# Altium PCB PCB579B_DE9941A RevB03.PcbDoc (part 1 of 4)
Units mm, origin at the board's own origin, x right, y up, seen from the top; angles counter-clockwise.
Board outline 85.8 x 54.18 mm, 6 copper layers (Top, L2C, L3C, L4C, L5C, Bottom), stack 1.627 mm thick; 536 components, 371 nets, 1413 pads, 798 vias.
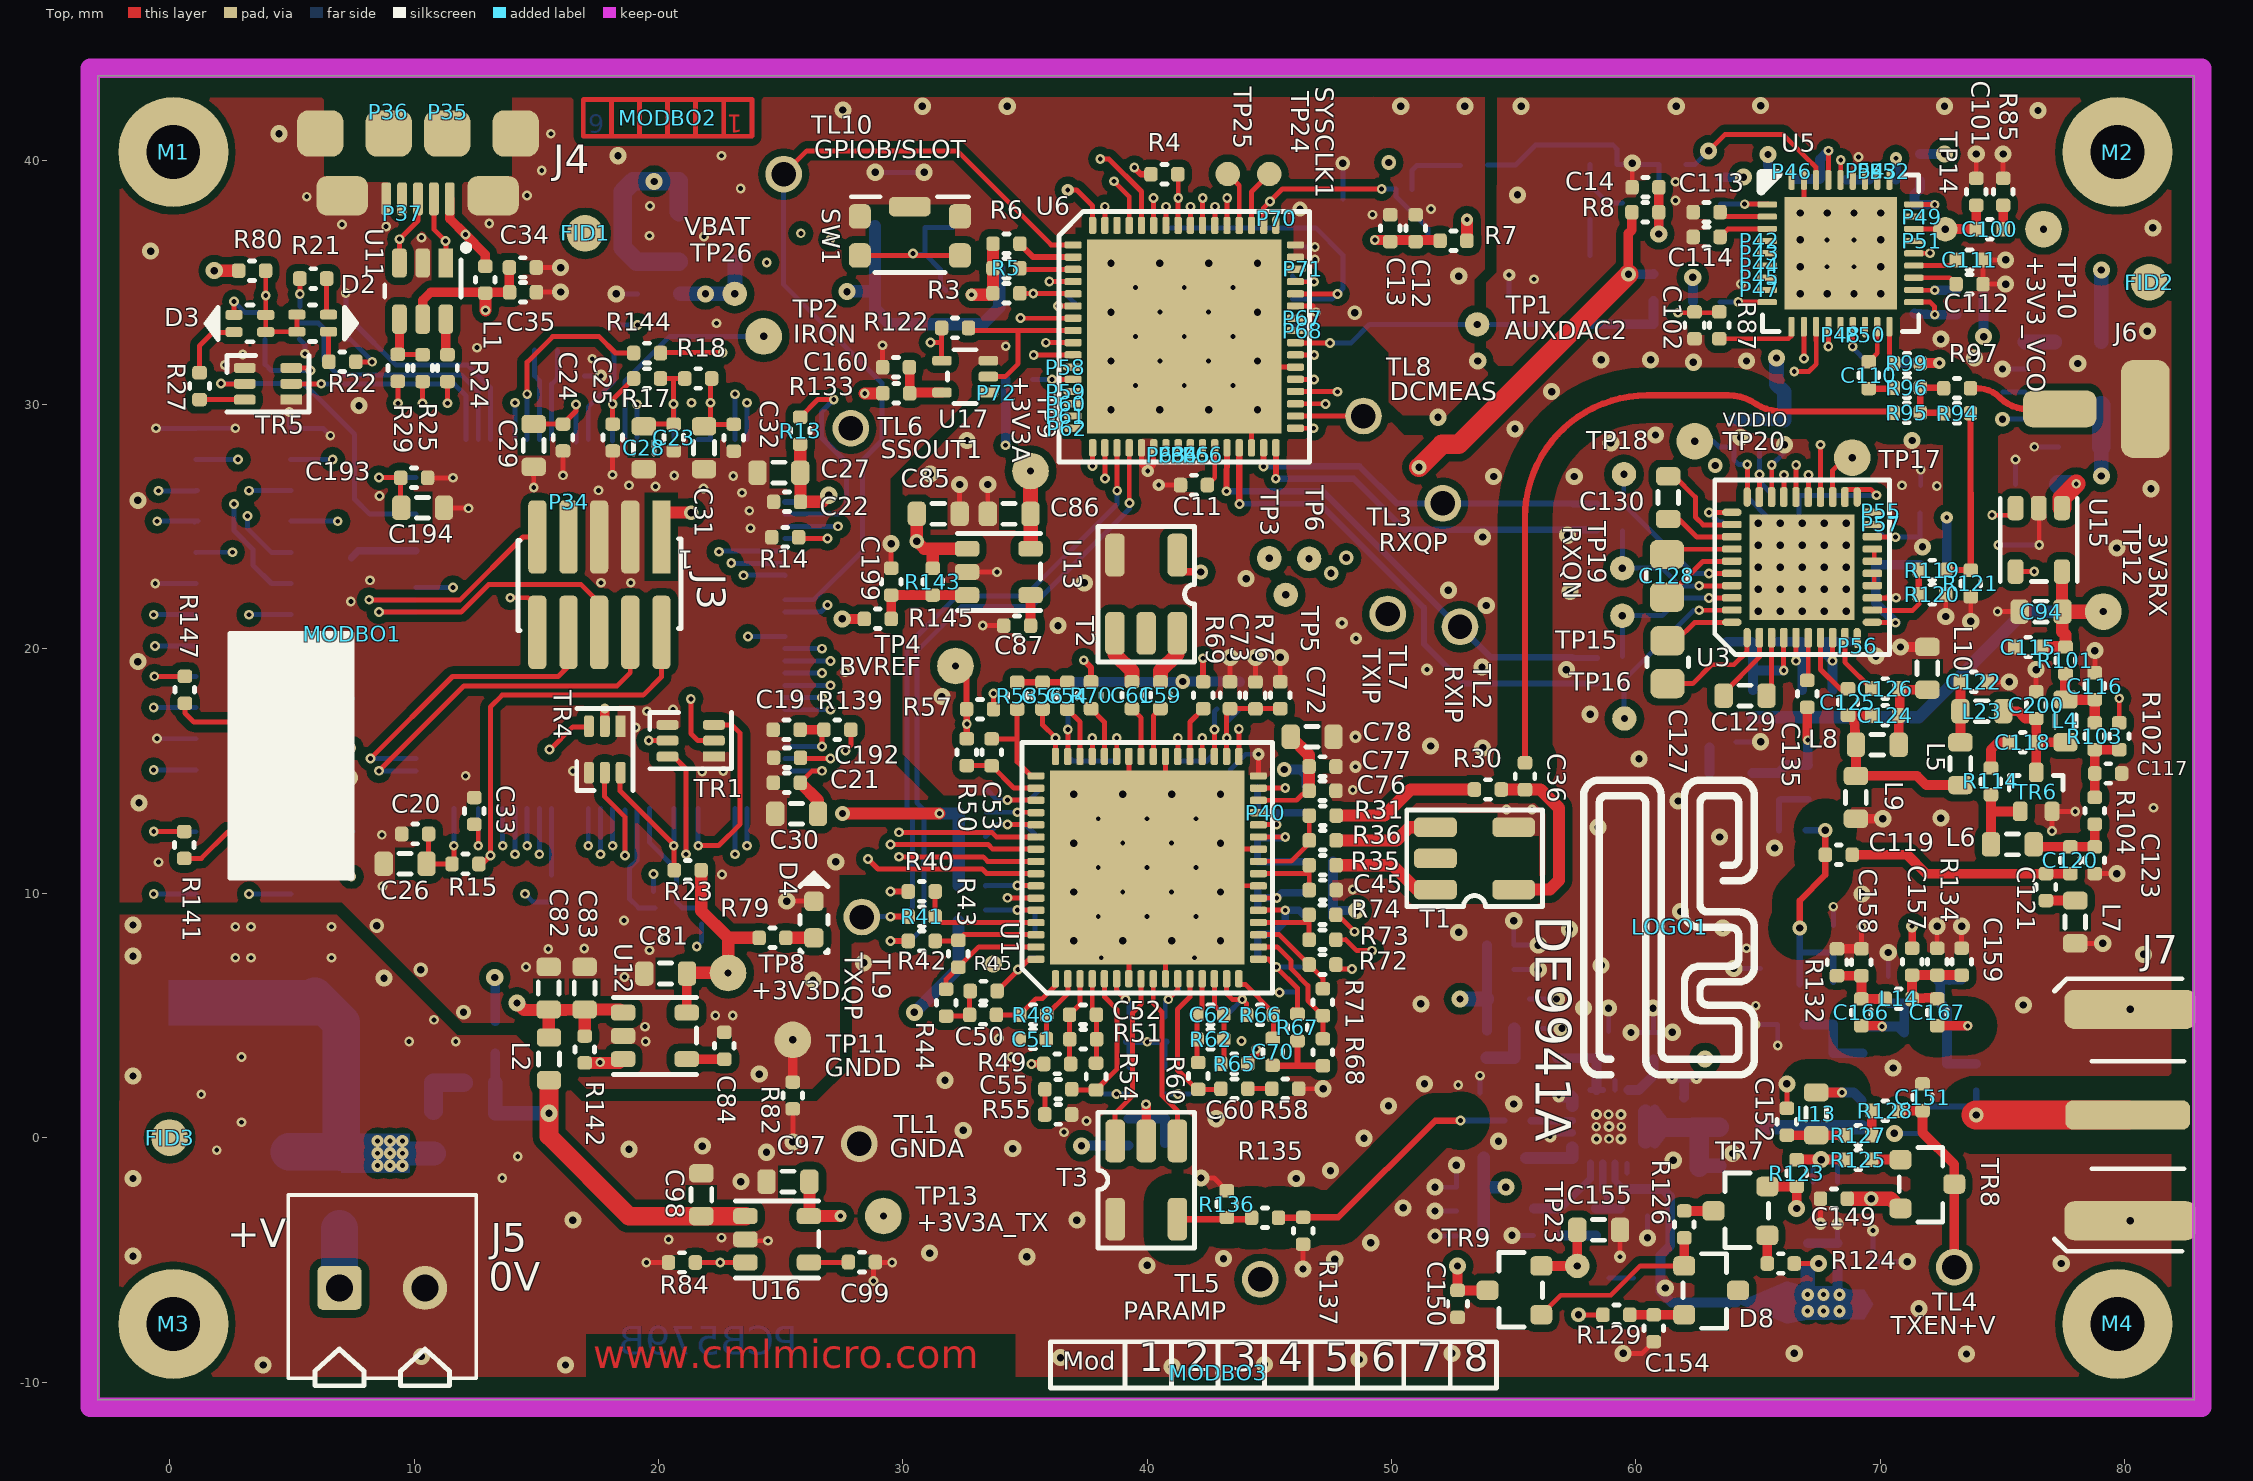
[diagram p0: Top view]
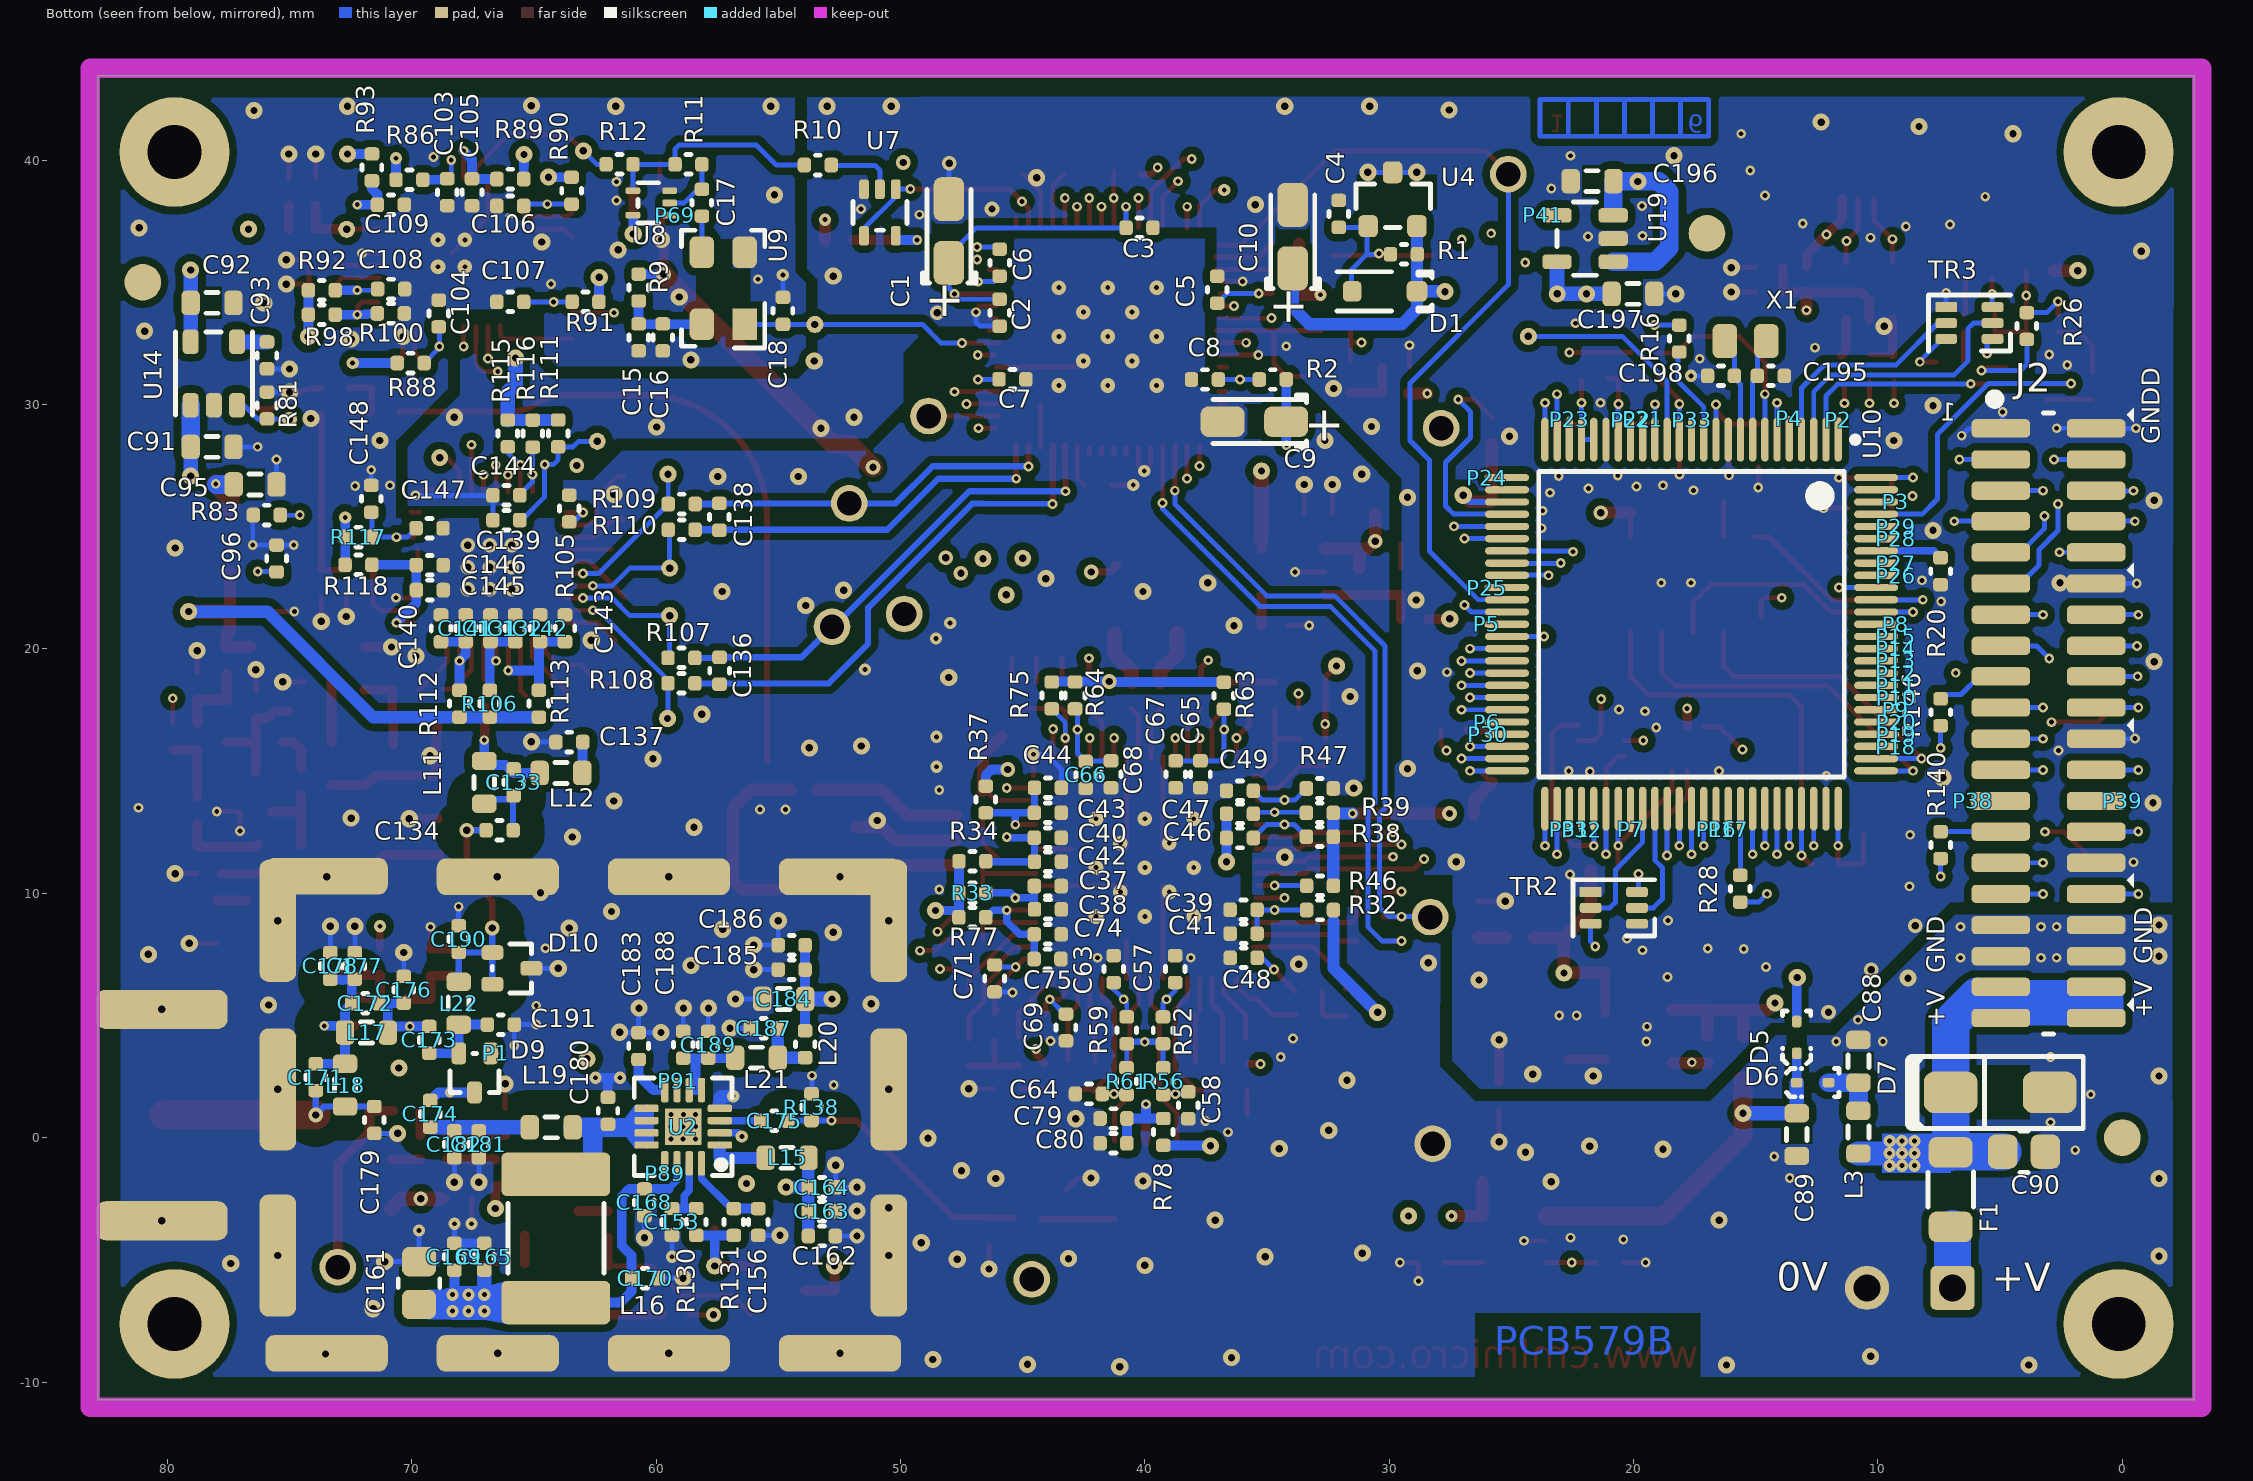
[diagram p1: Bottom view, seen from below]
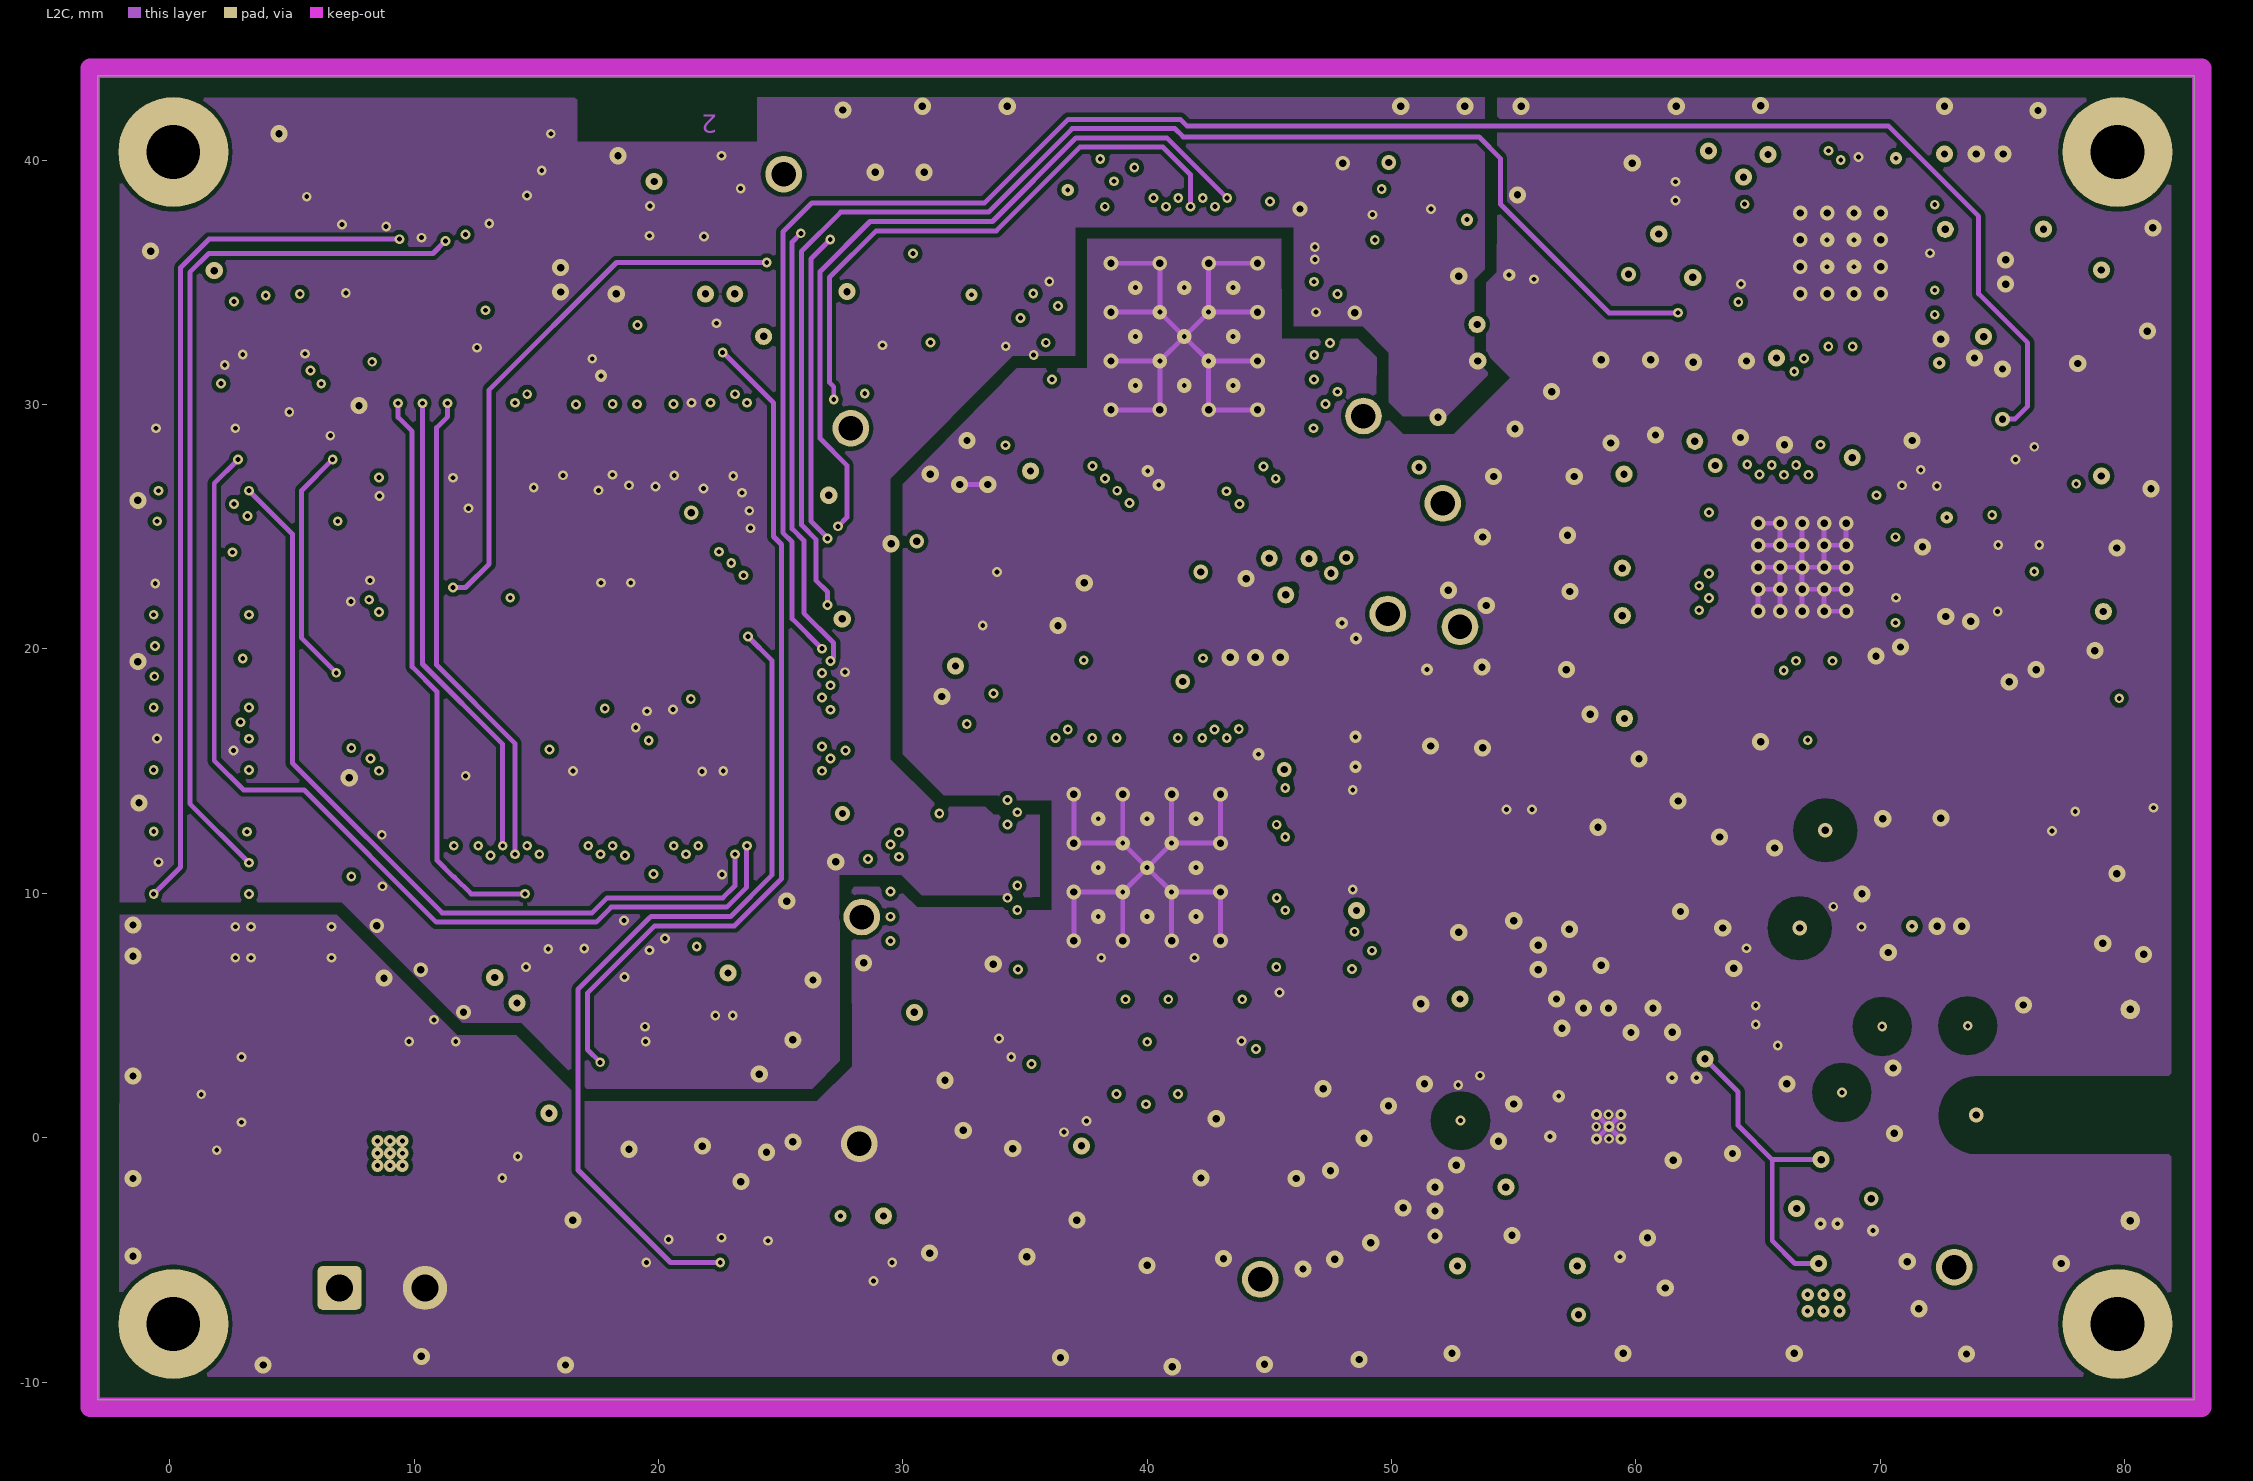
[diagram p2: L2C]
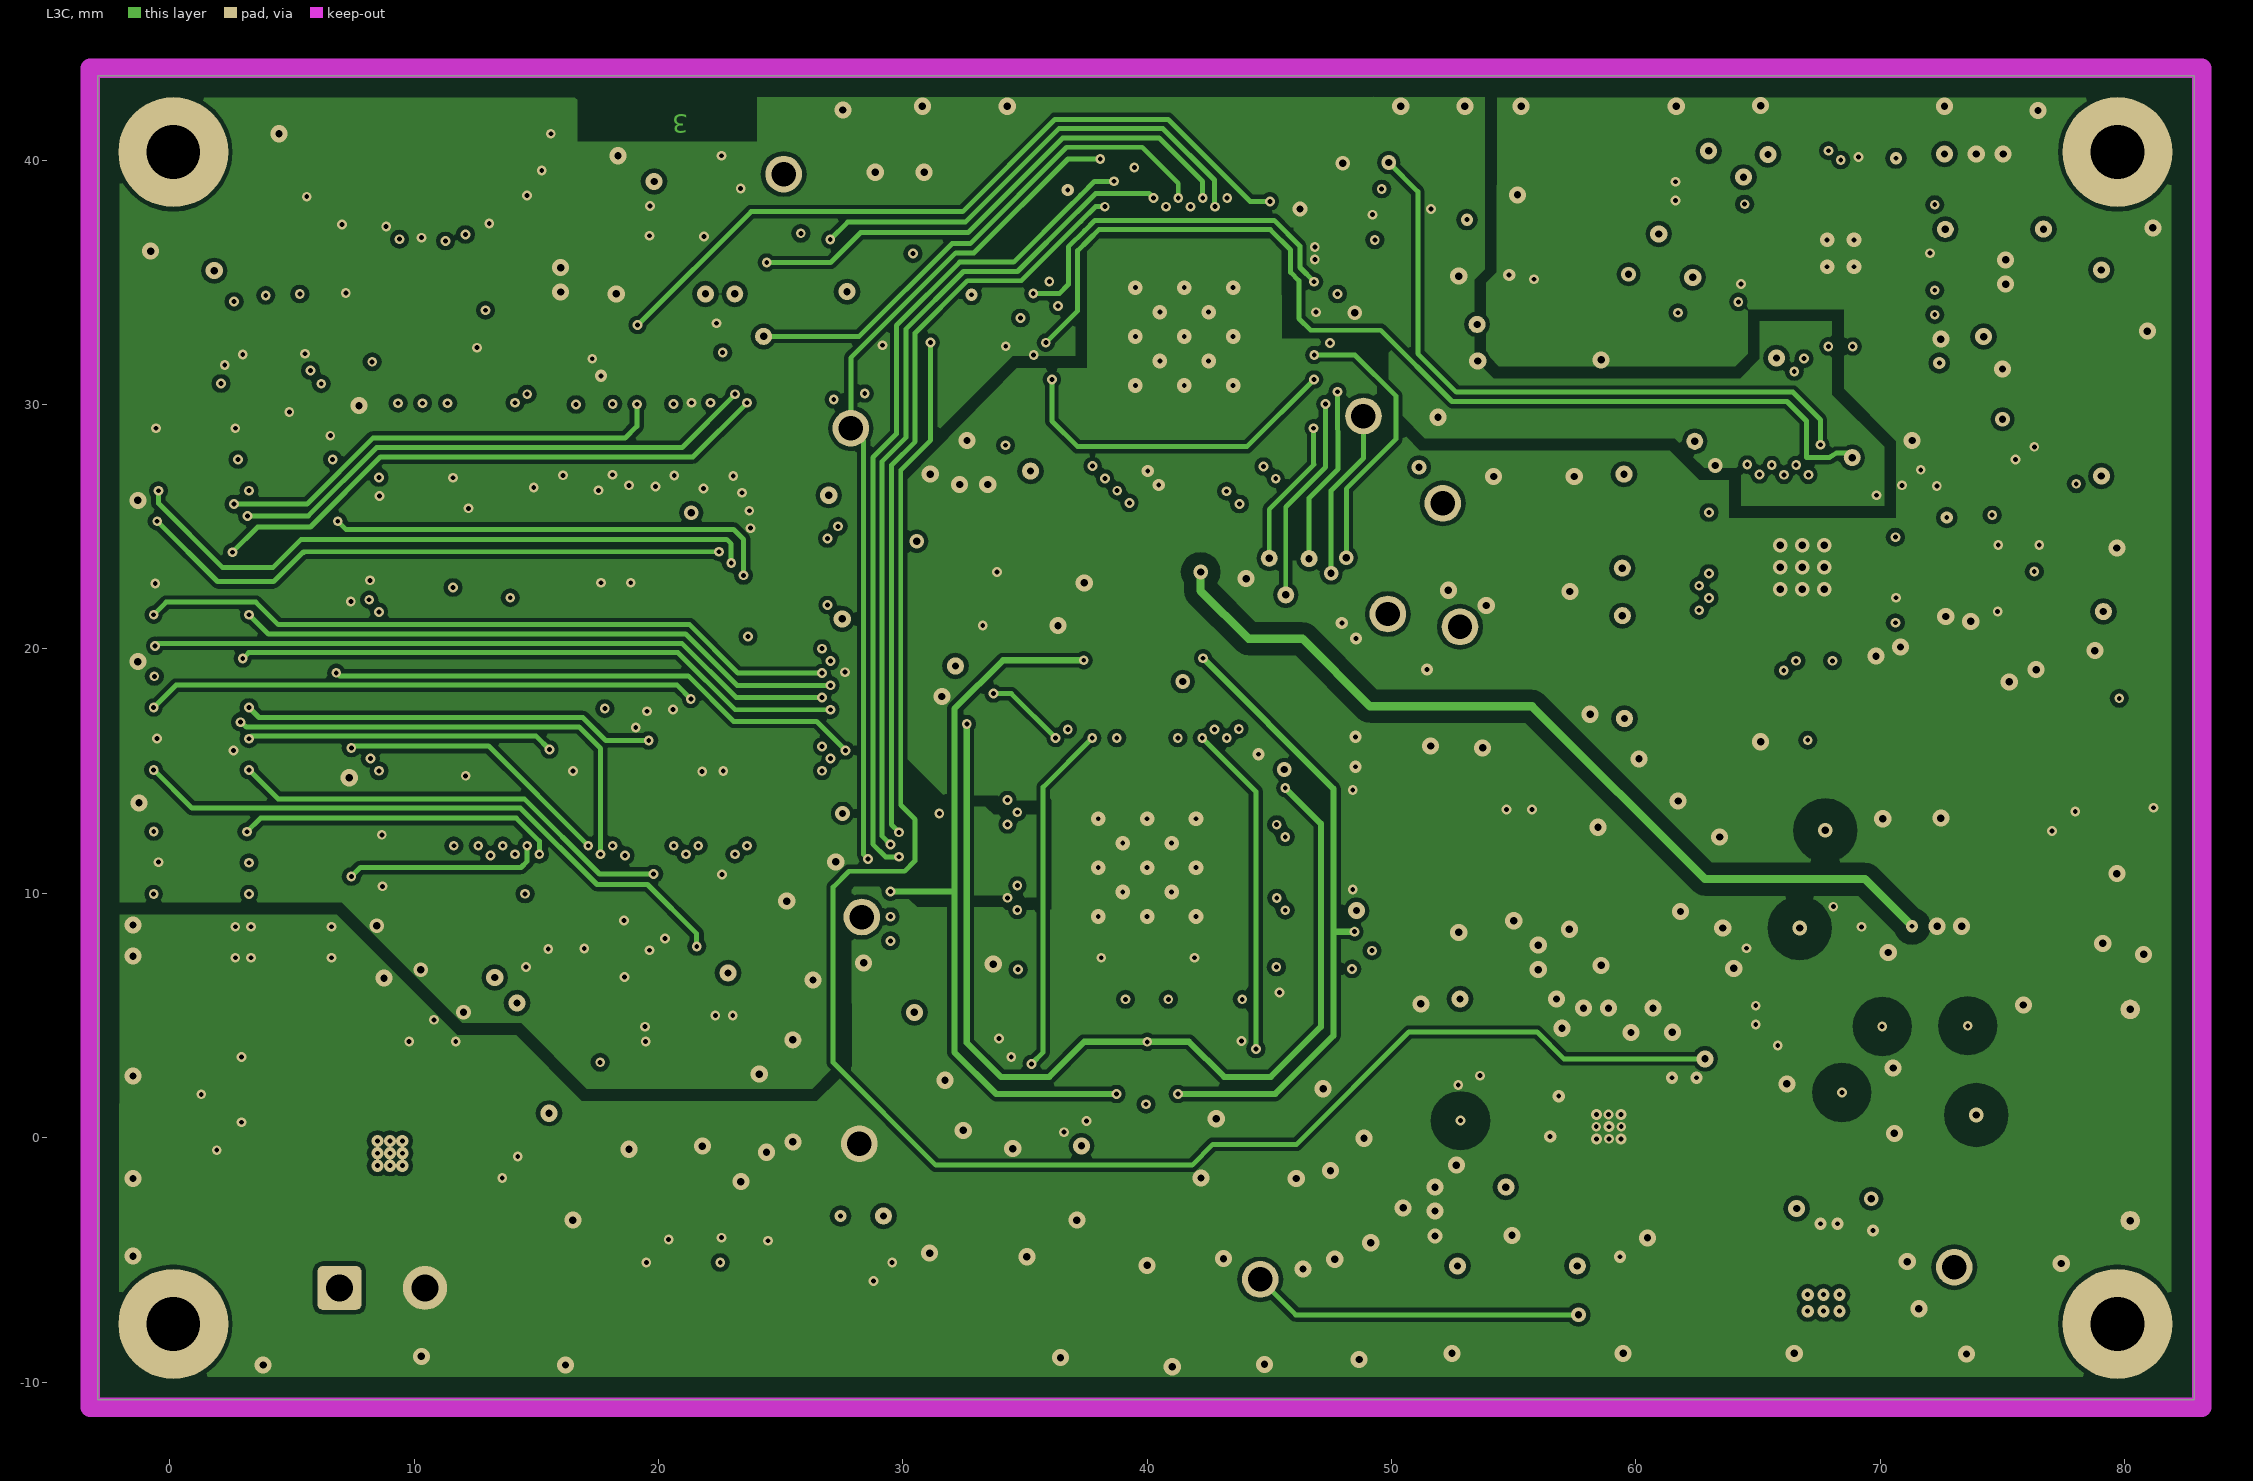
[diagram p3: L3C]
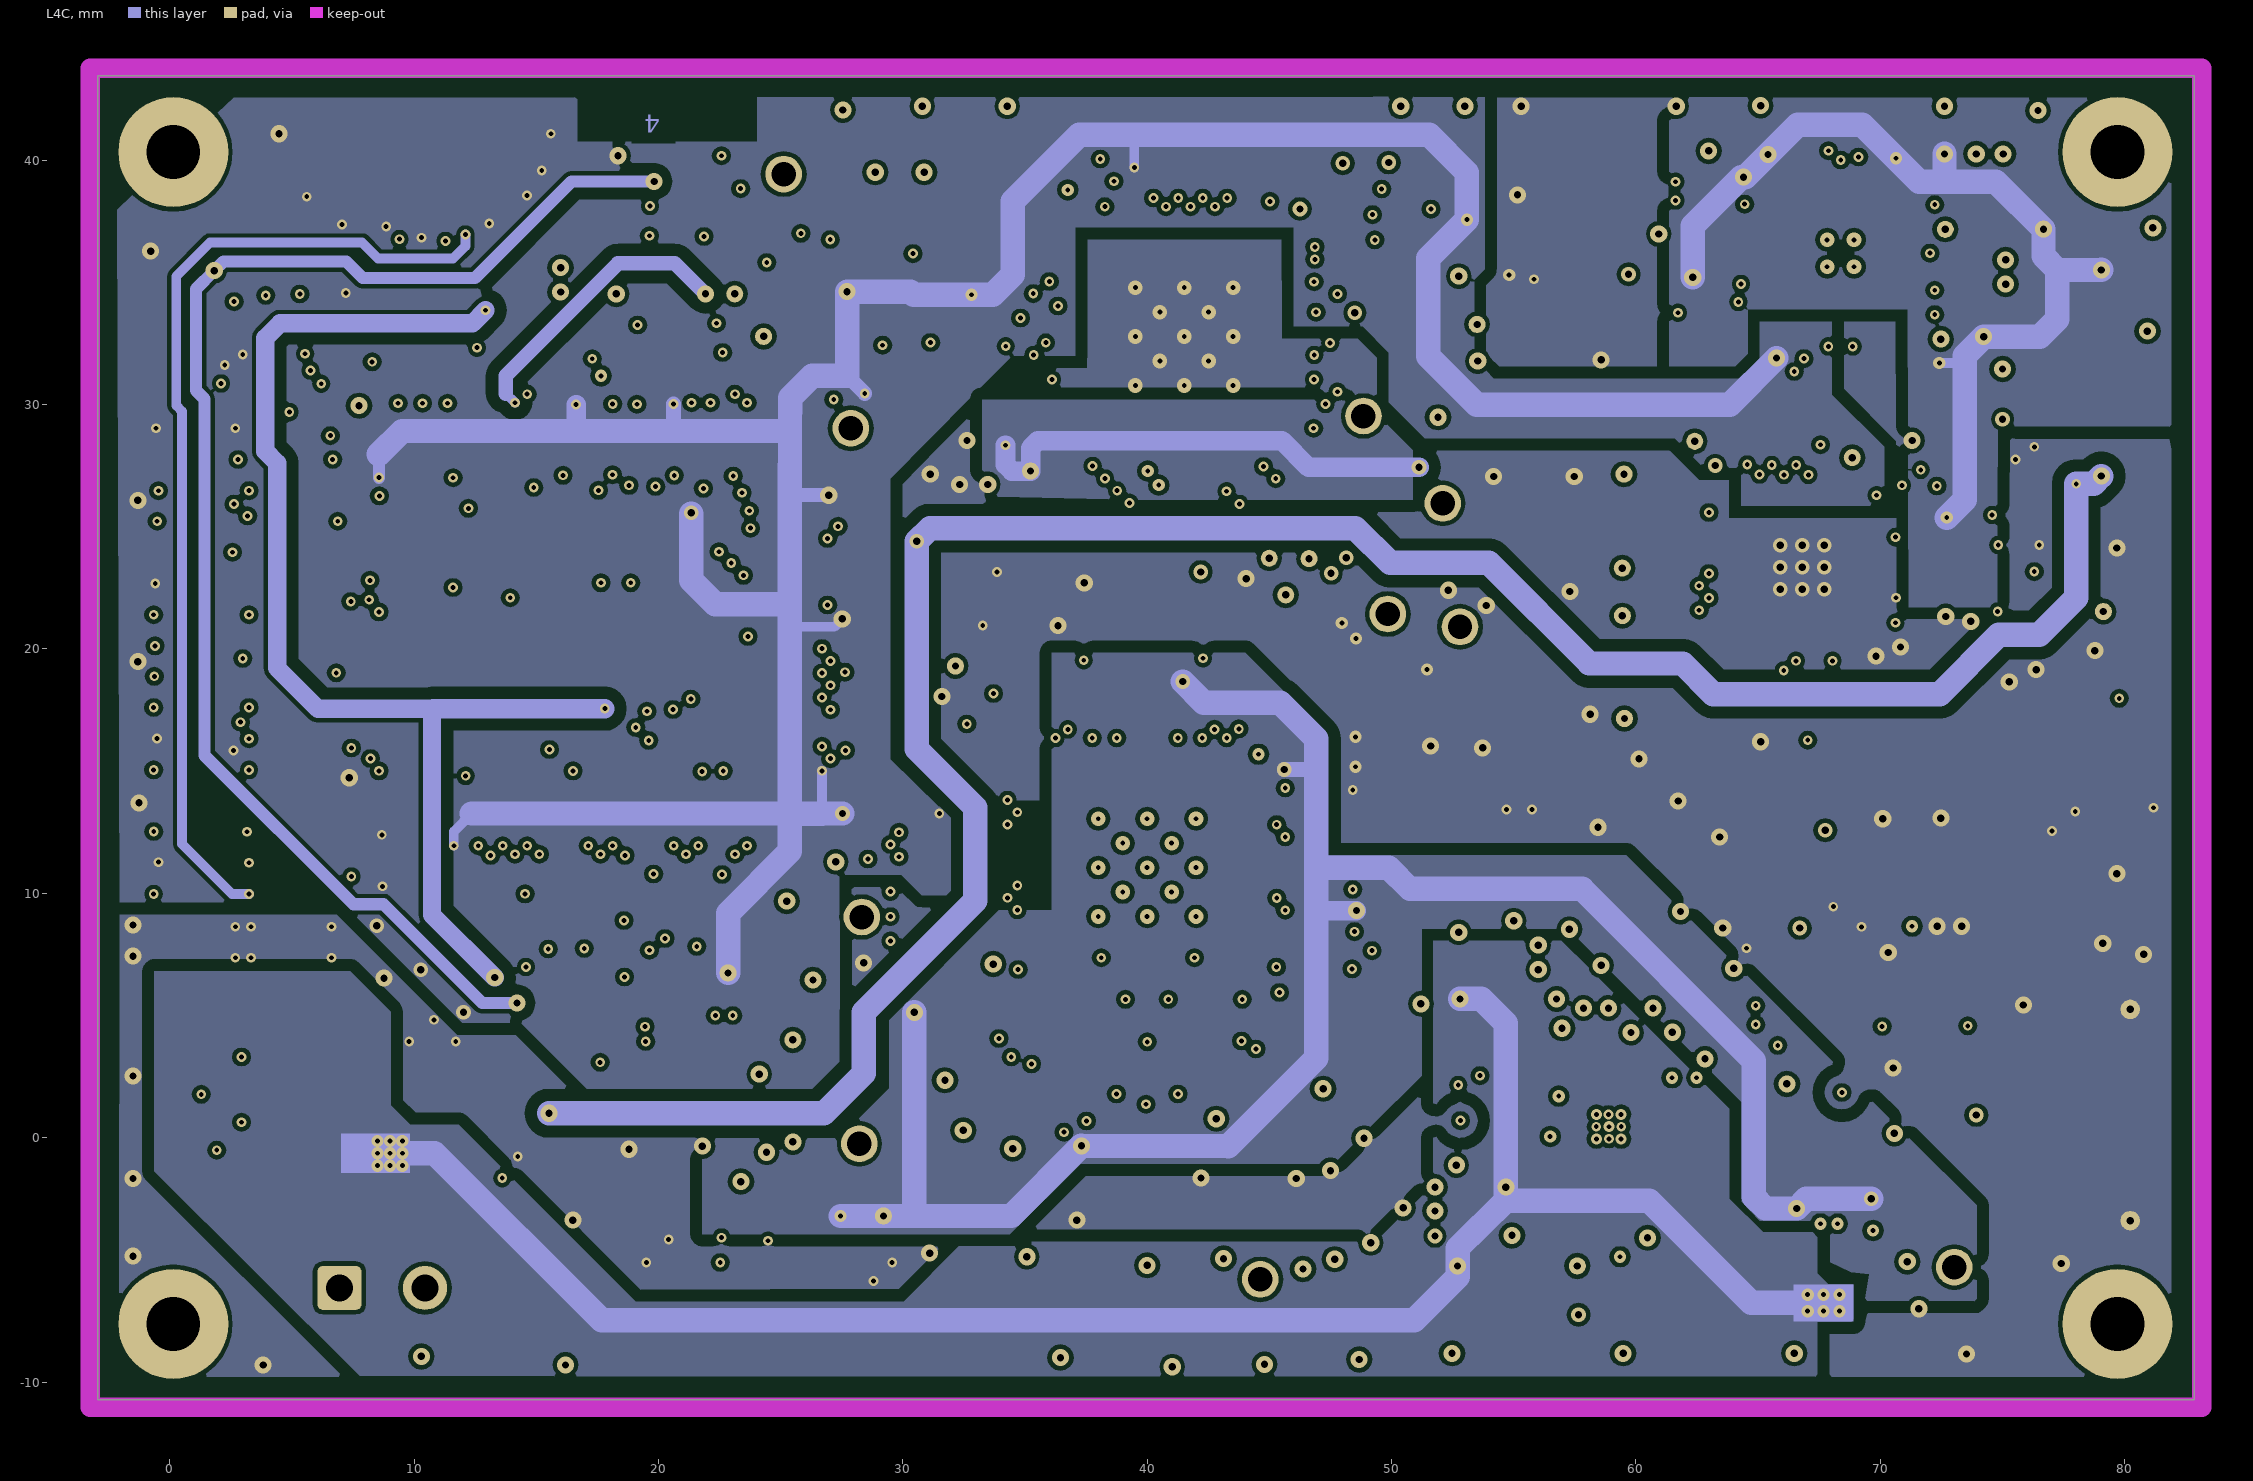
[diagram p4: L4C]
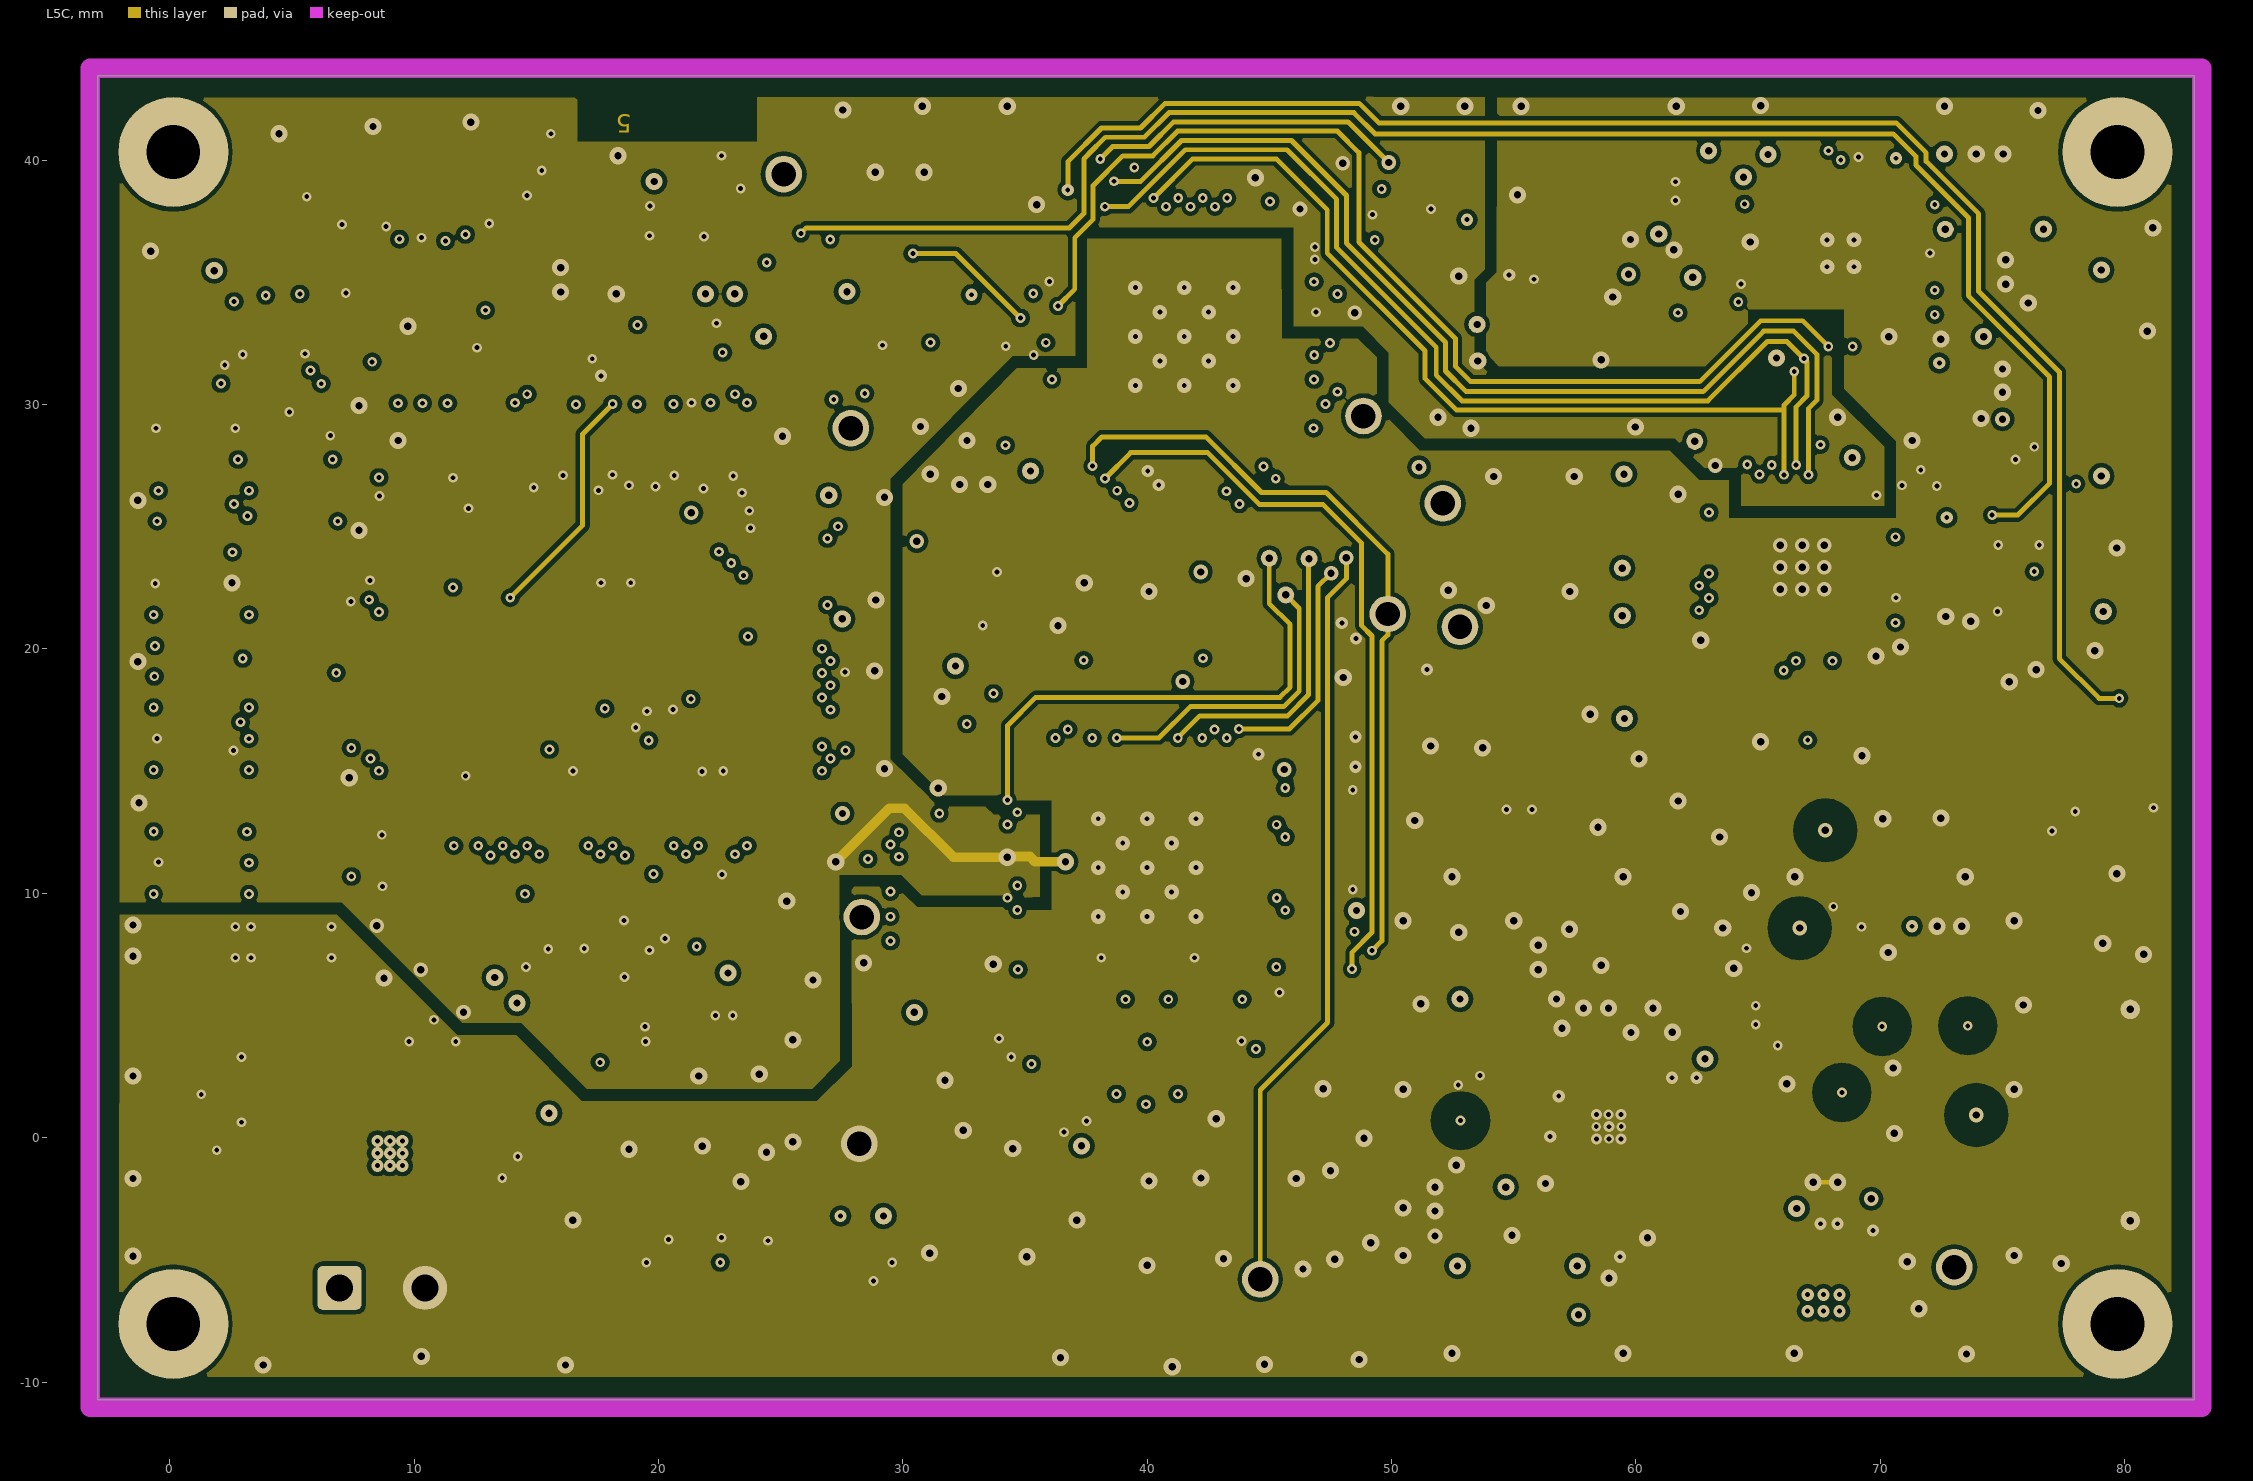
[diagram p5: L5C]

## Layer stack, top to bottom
Top: signal copper 0.037
Dielectric: core 0.1538, PCL370 HR, Dk 4.2
L2C: signal copper 0.018
Dielectric: prepreg 0.41, FR-4, Dk 4.3
L3C: signal copper 0.018
Dielectric: core 0.3548, PCL370 HR, Dk 4.2
L4C: signal copper 0.018
Dielectric: prepreg 0.41, FR-4, Dk 4.3
L5C: signal copper 0.018
Dielectric: core 0.152, PCL370 HR, Dk 4.2
Bottom: signal copper 0.037

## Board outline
-2.949,-10.724 -2.949,43.454 82.852,43.454 82.852,-10.724

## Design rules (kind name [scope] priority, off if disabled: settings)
Clearance Clearance_50_Ohm [InNetClass('50 OHM') vs InPolygonClass('50OHM_Clearance')] p1: gap=1
Clearance Clearance_Top-GNDD [InNamedPolygon('Top-GNDD')] p2: gap=0.3
Clearance Clearance_Top-GNDA [InNamedPolygon('Top-GNDA')] p3: gap=0.3
Clearance Clearance_Bot-GNDA [InNamedPolygon('Bot-GNDA')] p4: gap=0.3
Clearance Clearance_L4C-GND [InNamedPolygon('L4C-GND') vs OnLayer('L4C')] p5: gap=0.5
Clearance Clearance_L4C-3V3D [InNamedPolygon('L4C-3V3D') vs OnLayer('L4C')] p6: gap=0.5
Clearance Clearance_L3C-GND [InNamedPolygon('L3C-GNDA') vs InNet('PA_FEEDBACK')] p7: gap=0.5
Clearance Clearance_Bot-GNDD [InNamedPolygon('Bot-GNDD')] p8: gap=0.3
Clearance FiducialClearance [(InPadClass('Fiducial'))] p9: gap=0.5
Clearance Clearance_Cu_PadToPad [OnCopper And IsPad vs OnCopper And IsPad] p10: gap=0.178
Clearance Clearance_Cu_PadToLine [OnCopper And IsPad vs OnCopper And IsWire] p11: gap=0.178
Clearance Clearance_Cu_LineToLine [OnCopper And IsWire vs OnCopper And IsWire] p12: gap=0.178
Clearance Clearance_Cu_ViaToPad [OnCopper And IsVia vs OnCopper And IsPad] p13: gap=0.178
Clearance Clearance_Cu_ViaToLine [OnCopper And IsVia vs OnCopper And IsWire] p14: gap=0.178
Clearance Clearance_Cu_ViaToVia [OnCopper And IsVia vs OnCopper And IsVia] p15: gap=0.178
Clearance Clearance_Design_HoleToHole [(IsVia Or IsThruPin) vs (IsVia Or IsThruPin)] p16: gap=0.178
Clearance Clearance_Region_All [(IsRegion AND NOT (InComponentClass('All Components')))] p17: gap=0.178
ComponentClearance [All] p1 off: gap=0.254 collisioncheckmode=3 verticalgap=0.254 showdistances=FALSE
DiffPairsRouting [All] p1 off: maxlimit=0.254 minlimit=0.2 mostfreqgap=0.2 maxuncoupledlength=12.7
FabricationTestPointUsage TestPointUsage [All] p1 off: valid=0 allowmultiple=FALSE
FabricationTestpoint Testpoint [(IsPad And (OnTopLayer Or OnBottomLayer))] p1 off: side=3 testpointundercomponent=TRUE minsize=1.016 maxsize=2.54 preferedsize=1.524 minholesize=0 maxholesize=1.016 preferedholesize=0.813 testpointgrid=0.025 allowsidetop=TRUE allowsidebottom=TRUE usegrid=TRUE gridtolerance=0
FanoutControl Fanout_BGA [IsBGA] p1 off: bgadir=Out bgaviamode=Centered fanoutstyle=Auto fanoutdirection=Alternating viagrid=0.025 // Fanout_BGA (Default Rule)
FanoutControl Fanout_LCC [IsLCC] p2 off: bgadir=Out bgaviamode=Centered fanoutstyle=Auto fanoutdirection=Alternating viagrid=0.025 // Fanout_LCC (Default Rule)
FanoutControl Fanout_SOIC [IsSOIC] p3 off: bgadir=Out bgaviamode=Centered fanoutstyle=Auto fanoutdirection=Alternating viagrid=0.025 // Fanout_SOIC (Default Rule)
FanoutControl Fanout_Small [(CompPinCount < 5)] p4 off: bgadir=Out bgaviamode=Centered fanoutstyle=Auto fanoutdirection=OutThenIn viagrid=0.025 // Fanout_Small (Default Rule)
FanoutControl Fanout_Default [All] p5 off: bgadir=Out bgaviamode=Centered fanoutstyle=Auto fanoutdirection=Alternating viagrid=0.025 // Fanout_Default (Default Rule)
Height [All] p1 off: minheight=0 maxheight=25.4 prefheight=12.7
HoleSize [All] p1: absolutevalues=TRUE maxlimit=4 minlimit=0.025 maxpercent=80.000 minpercent=20.000
LayerPairs [All] p1 off: enforce=TRUE
MinimumSolderMaskSliver [All] p1: minsoldermaskwidth=0.075
PlaneClearance [All] p1: clearance=0.3
PlaneConnect [All] p1: planeconnectstyle=Direct reliefexpansion=0.508 reliefentries=4 reliefconductorwidth=0.254 reliefairgap=0.254
PolygonConnect PolygonConnect_VCO [All vs InPolygonClass('Poly2100') or InPolygonClass('Poly460') or InPolygonClass('Poly800')] p1: connectstyle=Direct reliefconductorwidth=0.254 reliefentries=4 polygonreliefangle="90 Angle"
PolygonConnect PolygonConnect_GNDA_Vias [IsVia vs InNet('GND') Or InNet('GNDD')] p2: connectstyle=Direct reliefconductorwidth=0.254 reliefentries=4 polygonreliefangle="90 Angle"
PolygonConnect [All] p3: connectstyle=Direct reliefconductorwidth=0.3 reliefentries=4 polygonreliefangle="90 Angle"
RoutingCorners [All] p1 off: cornerstyle=45-Degree minsetback=2.5 maxsetback=2.5
RoutingLayers [All] p1 off: top layer_v5=TRUE mid layer 1_v5=TRUE mid layer 2_v5=TRUE mid layer 4_v5=TRUE mid layer 5_v5=TRUE bottom layer_v5=TRUE
RoutingPriority [All] p1 off: routingpriority=0
RoutingTopology [All] p1 off: topology=Shortest
RoutingVias [All] p1: holewidth=0.3 width=0.6 viastyle="Through Hole" minholewidth=0.2 minwidth=0.4 maxholewidth=0.7 maxwidth=1.2
SilkToSilkClearance [All] p1 off: silktosilkclearance=0.15
SilkscreenOverComponentPads [IsPad] p1 off: minsilkscreentomaskgap=0.01
SolderMaskExpansion [All] p1: expansion=0.102
UnConnectedPin [All] p1 off:
Width Width_GNDA [InNet('GNDA')] p1: maxlimit=2 minlimit=0.2 preferedwidth=0.5 // For GNDA rings around VCOs
Width [All] p2: maxlimit=2 minlimit=0.19 preferedwidth=0.4 toplayer_maxwidth=1.2 midlayer1_maxwidth=0.8 midlayer1_prefwidth=0.2 midlayer2_maxwidth=1.2 midlayer4_minwidth=0.2 midlayer4_maxwidth=1.2 midlayer5_maxwidth=0.8 minimp=50.000000 maximp=50.000000 favimp=50.000000
7 further rules are at their usual default settings.

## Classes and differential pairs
component class z_PSU: C81 C82 C83 C84 C85 C86 C87 C88 C89 C90 C91 C92 C93 C94 C95 C96 C97 C98 C99 C196 C197 C199 D4 D5 D6 D7 F1 FID1 FID2 FID3 J5 L2 L3 LOGO1 M1 M2 M3 M4 MODBO1 MODBO2 MODBO3 P41 R79 R80 R81 R82 R83 R84 R142 R143 R144 R145 TL1 TP8 TP9 TP10 TP11 TP12 TP13 TP26 U12 U13 U14 U15 U16 U19
component class z_PA: C149 C150 C151 C152 C153 C154 C155 C156 C157 C158 C159 C160 C161 C162 C163 C164 C165 C166 C167 C168 C169 C170 C171 C172 C173 C174 C175 C176 C177 C178 C179 C180 C181 C182 C183 C184 C185 C186 C187 C188 C189 C190 C191 D8 D9 D10 J7 L13 L14 L15 L16 L17 L18 L19 L20 L21 L22 P1 P72 P89 P91 R122 R123 R124 R125 R126 R127 R128 R129 R130 R131 R132 R133 R134 R135 R136 R137 R138 TL4 TP23 TR7 TR8 TR9 U2 U17
component class z_CMX7341: C1 C2 C3 C4 C5 C6 C7 C8 C9 C10 C11 C12 C13 C14 C15 C16 C17 C18 D1 P58 P59 P60 P61 P62 P63 P64 P65 P66 P67 P68 P69 P70 P71 R1 R2 R3 R4 R5 R6 R7 R8 R9 R10 R11 R12 SW1 TL5 TL6 TL7 TL8 TL9 TL10 TP1 TP24 TP25 U4 U6 U7 U8 U9
component class z_CMX998: C36 C37 C38 C39 C40 C41 C42 C43 C44 C45 C46 C47 C48 C49 C50 C51 C52 C53 C54 C55 C56 C57 C58 C59 C60 C61 C62 C63 C64 C65 C66 C67 C68 C69 C70 C71 C72 C73 C74 C75 C76 C77 C78 C79 C80 P40 R30 R31 R32 R33 R34 R35 R36 R37 R38 R39 R40 R41 R42 R43 R44 R45 R46 R47 R48 R49 R50 R51 R52 R53 R54 R55 R56 R57 R58 R59 R60 R61 R62 R63 R64 R65 R66 R67 R68 R69 R70 R71 R72 R73 R74 R75 R76 R77 R78 T1 T2 T3 TP3 TP4 TP5 TP6 U1
component class z_CMX994: C115 C116 C117 C118 C119 C120 C121 C122 C123 C124 C125 C126 C127 C128 C129 C130 C131 C132 C133 C134 C135 C136 C137 C138 C139 C140 C141 C142 C143 C144 C145 C146 C147 C148 C200 L4 L5 L6 L7 L8 L9 L10 L11 L12 L23 P55 P56 P57 R101 R102 R103 R104 R105 R106 R107 R108 R109 R110 R111 R112 R113 R114 R115 R116 R117 R118 R119 R120 R121 TL2 TL3 TP15 TP16 TP17 TP18 TP19 TP20 TR6 U3
component class z_ARM: C19 C20 C21 C22 C23 C24 C25 C26 C27 C28 C29 C30 C31 C32 C33 C34 C35 C192 C193 C194 C195 C198 D2 D3 J2 J3 J4 L1 P2 P3 P4 P5 P6 P7 P8 P9 P10 P11 P12 P13 P14 P15 P16 P17 P18 P19 P20 P21 P22 P23 P24 P25 P26 P27 P28 P29 P30 P31 P32 P33 P34 P35 P36 P37 P38 P39 R13 R14 R15 R16 R17 R18 R20 R21 R22 R23 R24 R25 R26 R27 R28 R29 R139 R140 R141 R146 R147 TP2 TR1 TR2 TR3 TR4 TR5 U10 U11 X1
component class Synth: C100 C101 C102 C103 C104 C105 C106 C107 C108 C109 C110 C111 C112 C113 C114 J6 P42 P43 P44 P45 P46 P47 P48 P49 P50 P51 P52 P53 P54 R85 R86 R87 R88 R89 R90 R91 R92 R93 R94 R95 R96 R97 R98 R99 R100 TP14 U5
polygon class 50OHM_Clearance: Bot-GNDA Bot-GNDD L2C-GNDA L2C-GNDD L3C-GNDA L3C-GNDD L4C-3V3_VCO L4C-+V L4C-GNDD L4C_3V3A_TX L5C-GNDA L5C-GNDD Top-GNDA Top-GNDD
net class "50 Ohm": NetC110_1 NetC133_1 NetC166_1 NetC167_2 NetC171_2 NetC174_1 NetC174_2 NetC175_1 NetR94_1 PA_INPUT RX_LO RX_SWITCH TX_LO

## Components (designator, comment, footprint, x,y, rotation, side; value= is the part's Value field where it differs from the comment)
C1 "10uF 16V" TAJ_A_M 48.014,35.797 r90 bottom
C2 "10nF" 0402COM 45.942,34.303 r270 bottom
C3 "10nF" 0402COM 40.767,37.228 r180 bottom
C4 "100nF" 0402COM 32.064,37.247 r90 bottom
C5 "10nF" 0402COM 37.039,34.147 r90 bottom
C6 "10nF" 0402COM 45.942,35.253 r90 bottom
C7 "10nF" 0402COM 45.967,31.028 r180 bottom
C8 "10nF" 0402COM 36.989,31.022 r0 bottom
C9 "10uF 16V" TAJ_A_M 34.214,29.297 r0 bottom
C10 "10uF 16V" TAJ_A_M 33.948,35.566 r90 bottom
C11 "100nF" 0402COM 41.365,26.702 r0 top
C12 "10nF" 0402COM 50.985,36.661 r90 top
C13 "100pF" 0402COM 49.943,36.661 r90 top
C14 "1000pF" 0402COM 59.84,38.882 r0 top
C15 "10nF" 0402COM 60.714,32.194 r90 bottom
C16 "1000pF" 0402COM 59.723,33.294 r270 bottom
C17 "1000pF" 0402COM 58.123,37.706 r90 bottom
C18 "DNF" 0402COM 54.807,33.28 r90 bottom
C19 "2.2uF" 0402COM 24.697,16.691 r0 top
C20 "100nF" 0402COM 9.499,12.426 r0 top
C21 "100nF" 0402COM 24.704,14.522 r0 top
C22 "100nF" 0402COM 24.715,26.013 r0 top
C23 "100nF" 0402COM 20.629,28.097 r90 top
C24 "100nF" 0402COM 16.096,28.098 r90 top
C25 "100nF" 0402COM 18.129,28.097 r90 top
C26 "10uF" 0603COM 8.762,11.206 r0 top
C27 "10uF" 0603COM 24.053,27.208 r0 top
C28 "10uF" 0603COM 19.403,27.353 r90 top
C29 "10uF" 0603COM 14.896,27.448 r90 top
C30 "10uF" 0603COM 24.782,13.252 r0 top
C31 "10uF" 0603COM 21.867,27.353 r90 top
C32 "10nF" 0402COM 23.086,28.089 r90 top
C33 "2.2uF" 0402COM 12.469,13.916 r270 top
C34 "100nF" 0402COM 15.002,35.605 r180 top
C35 "10nF" 0402COM 13.91,34.589 r0 top
C36 "1000pF" 0402COM 55.46,15.337 r270 top
C37 "33pF" 0402COM 43.423,10.294 r0 bottom
C38 "10nF" 0402COM 43.414,9.339 r0 bottom
C39 "33pF" 0402COM 36.508,9.324 r180 bottom
C40 "33pF" 0402COM 43.423,12.269 r0 bottom
C41 "10nF" 0402COM 36.505,8.348 r180 bottom
C42 "10nF" 0402COM 43.414,11.295 r0 bottom
C43 "33pF" 0402COM 43.423,13.294 r0 bottom
C44 "10nF" 0402COM 43.414,14.317 r0 bottom
C45 "DNF" 0402COM 46.632,10.13 r0 top
C46 "10nF" 0402COM 36.658,12.26 r180 bottom
C47 "10nF" 0402COM 36.658,13.251 r180 bottom
C48 "470pF" 0402COM 36.505,7.358 r180 bottom
C49 "47nF" 0402COM 36.658,14.19 r180 bottom
C50 "1000pF" 0402COM 33.832,5.023 r180 top
C51 "100pF" 0402COM 34.773,4.035 r0 top
C52 "100pF" 0402COM 37.923,5.026 r180 top
C53 "470pF" 0402COM 33.636,16.316 r270 top
C54 "1000pF" 0402COM 36.734,17.535 r90 top
C55 "33nF" 0402COM 35.814,1.978 r0 top
C56 "220pF" 0402COM 35.718,17.535 r90 top
C57 "33nF" 0402COM 38.761,6.347 r90 bottom
C58 "33nF" 0402COM 38.225,1.875 r270 bottom
C59 "1000pF" 0402COM 40.544,18.655 r270 top
C60 "33nF" 0402COM 44.117,2.002 r180 top
C61 "1000pF" 0402COM 39.376,18.655 r270 top
C62 "100pF" 0402COM 43.137,5.026 r180 top
C63 "33nF" 0402COM 41.275,6.347 r90 bottom
C64 "33nF" 0402COM 41.738,1.787 r0 bottom
C65 "33pF" 0402COM 37.724,14.317 r90 bottom
C66 "33pF" 0402COM 42.421,14.294 r90 bottom
C67 "10nF" 0402COM 38.74,14.317 r90 bottom
C68 "10nF" 0402COM 41.382,14.317 r90 bottom
C69 "100pF" 0402COM 43.228,3.957 r90 bottom
C70 "1000pF" 0402COM 45.133,4.059 r270 top
C71 "470pF" 0402COM 46.149,5.964 r90 bottom
C72 "33pF" 0402COM 45.447,18.652 r270 top
C73 "10nF" 0402COM 43.389,18.655 r270 top
C74 "33pF" 0402COM 43.423,8.319 r0 bottom
C75 "10nF" 0402COM 43.432,7.31 r0 bottom
C76 "10nF" 0402COM 47.724,14.194 r180 top
C77 "1uF" 0402COM 47.724,15.184 r180 top
C78 "10uF" 0603COM 47.623,16.403 r180 top
C79 "33pF" 0402COM 41.831,0.782 r180 bottom
C80 "10nF" 0402COM 41.831,-0.234 r180 bottom
C81 "10uF" 0603COM 21.174,6.714 r180 top
C82 "10uF" 0603COM 15.509,5.241 r90 top
C83 "1uF" 0603COM 16.983,5.241 r90 top
C84 "DNF" 0402COM 22.698,3.209 r90 top
C85 "1uF" 0603COM 30.575,25.525 r0 top
C86 "10uF" 0603COM 35.227,25.522 r180 top
C87 "DNF" 0402COM 35.227,20.95 r180 top
C88 "10uF" 0603COM 10.8,2.25 r90 bottom
C89 "10uF" 0603COM 13.325,1 r270 bottom
C90 "DNF" 0805COM 3.15,-0.575 r0 bottom
C91 "1uF" 0603COM 79.042,28.265 r180 bottom
C92 "10uF" 0603COM 79.042,34.158 r180 bottom
C93 "DNF" 0402COM 75.918,32.558 r270 bottom
C94 "10uF" 0603COM 77.45,21.525 r180 top
C95 "1uF" 0603COM 77.28,26.727 r180 bottom
C96 "DNF" 0402COM 75.528,23.146 r90 bottom
C97 "10uF" 0603COM 26.175,-1.8 r180 top
C98 "1uF" 0603COM 21.758,-3.21 r90 top
C99 "DNF" 0402COM 27.778,-5.09 r0 top
C100 "4.7nF" 0402COM 73.925,37.175 r0 top
C101 "180pF" 0402COM 73.925,38.15 r90 top
C102 "1000pF" 0402COM 62.396,33.788 r270 top
C103 "100nF" 0402COM 68.544,39.235 r270 bottom
C104 "100nF" 0402COM 68.889,33.172 r90 bottom
C105 "100nF" 0402COM 67.528,39.235 r270 bottom
C106 "100nF" 0402COM 65.414,38.122 r0 bottom
C107 "100nF" 0402COM 65.414,34.197 r0 bottom
C108 "100nF" 0402COM 71.389,34.722 r180 bottom
C109 "100nF" 0402COM 71.4,38.175 r180 bottom
C110 "1000pF" 0402COM 69.524,30.649 r90 top
C111 "100nF" 0402COM 73.1,35.914 r0 top
C112 "2.2uF" 0402COM 73.1,34.923 r0 top
C113 "100nF" 0402COM 63.44,37.871 r180 top
C114 "100nF" 0402COM 63.44,36.855 r180 top
C115 "10nF" 0402COM 75.5,20.075 r0 top
C116 "DNF" 0402COM 78.775,19.025 r270 top
C117 "10nF" 0402COM 79.875,14.9 r180 top
C118 "1000pF" 0402COM 76.375,16.175 r180 top
C119 "DNF" 0402COM 68.85,11.575 r180 top
C120 "10pF" 0402COM 77.775,11.9 r270 top
C121 "10pF" 0402COM 76.775,9.7 r90 top
C122 "DNF" 0402COM 74.375,18.65 r180 top
C123 "5.6pF" 0402COM 78.775,10.8 r90 top
C124 "3.3pF" 0402COM 70.75,17.275 r180 top
C125 "5.6pF" 0402COM 68.675,18.375 r270 top
C126 "1000pF" 0402COM 69.65,18.375 r0 top
C127 "2000pF" 0805COM 61.295,18.578 r90 top
C128 "2000pF" 0805COM 61.269,23.861 r270 top
C129 "1500pF" 0603COM 65.339,18.085 r180 top
C130 "1500pF" 0603COM 61.32,27.062 r270 top
C131 "33pF" 0402COM 66.774,21.39 r270 bottom
C132 "10nF" 0402COM 65.758,21.39 r270 bottom
C133 "1.5pF" 0402COM 65.828,13.988 r90 bottom
C134 "1000pF" 0402COM 65.85,12.575 r0 bottom
C135 "1000pF" 0402COM 67.009,18.711 r270 top
C136 "DNF" 0402COM 57.402,19.655 r270 bottom
C137 "6.8pF" 0402COM 64.098,16.186 r180 bottom
C138 "DNF" 0402COM 57.408,25.95 r270 bottom
C139 "10nF" 0402COM 66.673,25.268 r180 bottom
C140 "33pF" 0402COM 68.8,21.388 r270 bottom
C141 "10nF" 0402COM 67.79,21.39 r270 bottom
C142 "33pF" 0402COM 64.742,21.39 r270 bottom
C143 "10nF" 0402COM 63.726,21.39 r270 bottom
C144 "10nF" 0402COM 66.673,26.284 r180 bottom
C145 "33pF" 0402COM 68.707,22.405 r0 bottom
C146 "10nF" 0402COM 68.712,23.427 r0 bottom
C147 "33pF" 0402COM 68.718,24.938 r0 bottom
C148 "10nF" 0402COM 71.651,26.69 r270 bottom
C149 "100nF" 0402COM 67.55,-2.5 r0 top
C150 "100nF" 0402COM 52.7,-7.35 r90 top
C151 "1000pF" 0402COM 71.725,2.2 r270 top
C152 "1000pF" 0402COM 66.175,1.2 r270 top
C153 "10nF" 0402COM 59.35,-4 r90 bottom
C154 "10nF" 0402COM 60.725,-8.35 r90 top
C155 "1uF" 0603COM 59.35,-3.775 r180 top
C156 "10nF" 0402COM 55.814,-4.003 r90 bottom
C157 "56pF" 0402COM 71.3,6.65 r90 top
C158 "5.6pF" 0402COM 69.225,7.725 r270 top
C159 "5.6pF" 0402COM 73.325,7.75 r270 top
C160 "1000pF" 0402COM 29.172,31.526 r0 top
C161 "10uF" 0805COM 69.7,-5.075 r270 bottom
C162 "10nF" 0402COM 52.664,-4.025 r0 bottom
C163 "1000pF" 0402COM 52.664,-3.009 r0 bottom
C164 "330pF" 0402COM 52.664,-2.028 r0 bottom
C165 "10nF" 0402COM 67.025,-4.325 r270 bottom
C166 "0.5pF" 0402COM 69.225,4.575 r90 top
C167 "0.5pF" 0402COM 72.325,5.675 r270 top
C168 "47pF" 0402COM 60.475,-3.2 r90 bottom
C169 "47pF" 0402COM 68.25,-4.325 r270 bottom
C170 "1000pF" 0402COM 59.9,-5.75 r0 bottom
C171 "2.0pF" 0402COM 73.925,3.025 r270 bottom
C172 "1.5pF" 0402COM 71.35,5.5 r0 bottom
C173 "56pF" 0402COM 69.275,3.45 r90 bottom
C174 "56pF" 0402COM 69.239,0.422 r90 bottom
C175 "56pF" 0402COM 54.614,0.697 r0 bottom
C176 "5.6pF" 0402COM 70.325,6.6 r270 bottom
C177 "6.8pF" 0402COM 72.325,7.575 r270 bottom
C178 "5.6pF" 0402COM 73.325,7.575 r270 bottom
C179 "5.6pF" 0402COM 71.525,0.175 r90 bottom
C180 "DNF" 0402COM 61.964,1.647 r270 bottom
C181 "33pF" 0402COM 67.25,-0.825 r90 bottom
C182 "5.6pF" 0402COM 68.25,-0.825 r90 bottom
C183 "DNF" 0402COM 60.714,4.297 r270 bottom
C184 "1uF" 0603COM 55.65,5.675 r180 bottom
C185 "10nF" 0402COM 55,6.875 r180 bottom
C186 "1000pF" 0402COM 55,7.875 r180 bottom
C187 "4.7pF" 0402COM 56.139,4.472 r180 bottom
C188 "DNF" 0402COM 58.887,4.349 r270 bottom
C189 "DNF" 0402COM 57.862,4.349 r270 bottom
C190 "6.8pF" 0402COM 68.075,7.575 r90 bottom
C191 "6.8pF" 0402COM 66.9,4.625 r180 bottom
C192 "0R" 0402COM 25.815,15.548 r180 top
C193 "100nF" 0402COM 10.554,26.997 r180 top
C194 "10uF" 0603COM 11.229,25.772 r180 top
C195 "8.2pF" 0402COM 14.934,31.171 r180 bottom
C196 "1uF" 0603COM 20.826,39.136 r0 bottom
C197 "1uF" 0603COM 20.9,34.525 r180 bottom
C198 "8.2pF" 0402COM 16.974,31.171 r180 bottom
C199 "DNF" 0402COM 29.525,22.2 r90 top
C200 "5.6pF" 0402COM 76.375,18.25 r270 top
D1 "BAS16HT" SOD323 28.864,34.629 r0 bottom
D2 "HSMF-C165" HSMF-C16x 5.205,33.675 r0 top
D3 "HSMF-C165" HSMF-C16x 3.935,32.964 r180 top
D4 "Green" LED0603 26.363,8.174 r90 top
D5 "NSR05T40XV2" SOD-523 13.325,4.1 r90 bottom
D6 "NSR05T40XV2" SOD-523 12.675,2.25 r180 bottom
D7 "SMAJ5.0A+" "DO-214AC SMA" 7.025,1.85 r180 bottom
D8 "MMBD1503A" SOT23_M 61.975,-5.25 r270 top
D9 "BAR64-04W" SOT323 66.775,3.45 r0 bottom
D10 "BAR64-04W" SOT323 66.7,7.575 r270 bottom
F1 "MF-NSMF150" 1206COM 7.025,-3.65 r90 bottom
FID1 "Fiducial" "1.5MM Fiducial" 17,37 r0 top
FID2 "Fiducial" "1.5MM Fiducial" 81,35 r0 top
FID3 "Fiducial" "1.5MM Fiducial" 0,0 r0 top
J2 "20x2 SMT hdr" M50-3602042 4.976,29.022 r270 bottom
J3 "5+5-pin 1.27mm header" Hdr_SMT_5x2_1p27Unsh 17.574,22.628 r180 top
J4 "USB-MicroB" USB-MICRO-B-ZX62 10.164,41.088 r180 top locked
J5 "MKDS_2w_3.5mm" MKDS_2 6.95,-6.15 r0 top
J6 "PCB Pad" "RG178 PAD" 77.341,29.815 r90 top
J7 "SMA" SMA_ENDLAUNCH_J502 80.125,0.925 r270 top locked
L1 "10 Z" 0402COM 12.919,35.656 r270 top
L2 "600R" 0603COM 15.525,4.1 r270 top
L3 "600R" 0603COM 10.8,-0.65 r90 bottom
L4 "18nH" 0603COM 77.575,17.925 r270 top
L5 "DNF" 0603COM 73.275,16.175 r270 top
L6 "18nH" 0603COM 76.275,12 r180 top
L7 "68nH" 0603COM 77.975,9.7 r270 top
L8 "DNF" 0603COM 69,16.075 r0 top
L9 "27nH" 0603COM 69,13.05 r90 top
L10 "27nH" 0603COM 71.925,18.33 r90 top
L11 "27nH" 0603COM 67.028,13.663 r90 bottom
L12 "100nH" 0603COM 64.764,14.922 r180 bottom
L13 "100nH" 0603COM 67.375,1.85 r270 top
L14 "5.6nH" 0402COM 70.2,5.675 r0 top
L15 "18R" 0603COM 53.764,-0.828 r0 bottom
L16 "82nH" 1515SQ-82N 64.1,-4.125 r90 bottom
L17 "18nH" 0603COM 70.975,4.3 r0 bottom
L18 "18nH" 0603COM 72.725,3.025 r270 bottom
L19 "2.2nH" 0603COM 63.414,0.422 r0 bottom
L20 "0R" 0402COM 53.9,4.375 r270 bottom
L21 "4.7nH" 0603COM 55.014,3.272 r0 bottom
L22 "18nH" 0603COM 68.075,4.625 r90 bottom
L23 "12nH" 0603COM 75.025,17.45 r180 top
LOGO1 "CML_LOGO" CML_LOGO 61.375,8.625 r270 top
M1 "2mm Hole" 2.2mmHole 0.15,40.325 r0 top locked
M2 "2mm Hole" 2.2mmHole 79.7,40.325 r0 top
M3 "2mm Hole" 2.2mmHole 0.15,-7.625 r0 top
M4 "2mm Hole" 2.2mmHole 79.7,-7.625 r0 top
MODBO1 "Serial number box" Serial-small 7.475,20.625 r270 top
MODBO2 "6 Layer PCB" 6LAYERBOX-SML 20.375,41.725 r180 top
MODBO3 "MODBOX_1-8" MOD1-8_BOX 42.9,-9.625 r0 top
P1 "PCB Pad" TINYPAD 66.55,3.45 r90 bottom
P2 "PCB Pad" TINYPAD 11.625,29.375 r90 bottom
P3 "PCB Pad" TINYPAD 9.275,26.025 r90 bottom
P4 "PCB Pad" TINYPAD 13.625,29.425 r90 bottom
P5 "PCB Pad" TINYPAD 26,21 r90 bottom
P6 "PCB Pad" TINYPAD 26,17 r90 bottom
P7 "PCB Pad" TINYPAD 20.125,12.6 r90 bottom
P8 "PCB Pad" TINYPAD 9.275,21 r90 bottom
P9 "PCB Pad" TINYPAD 9.275,17.5 r180 bottom
P10 "PCB Pad" TINYPAD 9.25,18 r180 bottom
P11 "PCB Pad" TINYPAD 9.275,18.5 r90 bottom
P12 "PCB Pad" TINYPAD 9.275,19 r90 bottom
P13 "PCB Pad" TINYPAD 9.275,19.525 r90 bottom
P14 "PCB Pad" TINYPAD 9.275,20 r90 bottom
P15 "PCB Pad" TINYPAD 9.275,20.5 r90 bottom
P16 "PCB Pad" TINYPAD 16.625,12.625 r90 bottom
P17 "PCB Pad" TINYPAD 16.125,12.6 r90 bottom
P18 "PCB Pad" TINYPAD 9.275,16 r90 bottom
P19 "PCB Pad" TINYPAD 9.25,16.5 r180 bottom
P20 "PCB Pad" TINYPAD 9.25,17 r180 bottom
P21 "PCB Pad" TINYPAD 19.625,29.425 r90 bottom
P22 "PCB Pad" TINYPAD 20.125,29.375 r90 bottom
P23 "PCB Pad" TINYPAD 22.625,29.4 r90 bottom
P24 "PCB Pad" TINYPAD 26,27 r90 bottom
P25 "PCB Pad" TINYPAD 26,22.5 r90 bottom
P26 "PCB Pad" TINYPAD 9.275,23 r90 bottom
P27 "PCB Pad" TINYPAD 9.275,23.5 r90 bottom
P28 "PCB Pad" TINYPAD 9.275,24.5 r90 bottom
P29 "PCB Pad" TINYPAD 9.275,25 r90 bottom
P30 "PCB Pad" TINYPAD 25.975,16.5 r90 bottom
P31 "PCB Pad" TINYPAD 22.625,12.625 r90 bottom
P32 "PCB Pad" TINYPAD 22.125,12.6 r90 bottom
P33 "PCB Pad" TINYPAD 17.625,29.375 r90 bottom
P34 "PCB Pad" TINYPAD 16.325,26.025 r90 top
P35 "PCB Pad" TINYPAD 11.375,41.975 r0 top
P36 "PCB Pad" TINYPAD 8.95,41.975 r0 top
P37 "PCB Pad" TINYPAD 9.525,37.825 r90 top
P38 "PCB Pad" TINYPAD 6.125,13.775 r0 bottom
P39 "PCB Pad" TINYPAD 0,13.775 r0 bottom
P40 "PCB Pad" TINYPAD 44.825,13.3 r90 top
P41 "PCB Pad" TINYPAD 23.725,37.75 r90 bottom
P42 "PCB Pad" TINYPAD 65.05,36.7 r90 top
P43 "PCB Pad" TINYPAD 65.05,36.2 r90 top
P44 "PCB Pad" TINYPAD 65.05,35.675 r180 top
P45 "PCB Pad" TINYPAD 65.05,35.175 r180 top
P46 "PCB Pad" TINYPAD 66.375,39.55 r180 top
P47 "PCB Pad" TINYPAD 65.05,34.7 r180 top
P48 "PCB Pad" TINYPAD 68.375,32.85 r180 top
P49 "PCB Pad" TINYPAD 71.7,37.675 r180 top
P50 "PCB Pad" TINYPAD 69.375,32.85 r180 top
P51 "PCB Pad" TINYPAD 71.7,36.675 r90 top
P52 "PCB Pad" TINYPAD 70.375,39.55 r90 top
P53 "PCB Pad" TINYPAD 69.875,39.55 r0 top
P54 "PCB Pad" TINYPAD 69.375,39.55 r0 top
P55 "PCB Pad" TINYPAD 70.025,25.6 r90 top
P56 "PCB Pad" TINYPAD 69.05,20.125 r90 top
P57 "PCB Pad" TINYPAD 70.025,25.1 r90 top
P58 "PCB Pad" TINYPAD 36.65,31.525 r90 top
P59 "PCB Pad" TINYPAD 36.675,30.525 r90 top
P60 "PCB Pad" TINYPAD 36.675,30.025 r90 top
P61 "PCB Pad" TINYPAD 36.675,29.525 r90 top
P62 "PCB Pad" TINYPAD 36.7,29.025 r90 top
P63 "PCB Pad" TINYPAD 40.775,27.95 r180 top
P64 "PCB Pad" TINYPAD 41.275,27.95 r180 top
P65 "PCB Pad" TINYPAD 41.775,27.95 r180 top
P66 "PCB Pad" TINYPAD 42.275,27.95 r180 top
P67 "PCB Pad" TINYPAD 46.35,33.525 r90 top
P68 "PCB Pad" TINYPAD 46.35,33.025 r90 top
P69 "PCB Pad" TINYPAD 59.225,37.75 r90 bottom
P70 "PCB Pad" TINYPAD 45.275,37.625 r90 top
P71 "PCB Pad" TINYPAD 46.375,35.525 r90 top
P72 "PCB Pad" TINYPAD 33.825,30.475 r90 top
P89 "PCB Pad" TINYPAD 59.639,-1.453 r270 bottom
P91 "PCB Pad" TINYPAD 59.112,2.331 r90 bottom
R1 "100k" 0402COM 28.847,36.144 r0 bottom
R2 "0R" 0402COM 34.214,31.022 r0 bottom
R3 "0R" 0402COM 33.689,34.547 r0 top
R4 "100k" 0402COM 41.255,39.423 r180 top
R5 "100k" 0402COM 34.789,35.572 r180 top
R6 "100k" 0402COM 34.792,36.578 r180 top
R7 "10R" 0402COM 53.084,36.698 r180 top
R8 "10R" 0402COM 60.932,37.866 r180 top
R9 "10R" 0402COM 60.714,34.234 r90 bottom
R10 "470R" 0402COM 53.93,39.797 r180 bottom
R11 "100k" 0402COM 58.123,39.822 r0 bottom
R12 "47R" 0402COM 60.942,39.822 r0 bottom
R13 "100k" 0402COM 25.8,29.475 r270 top
R14 "100k" 0402COM 24.639,24.565 r0 top
R15 "100k" 0402COM 11.554,11.198 r0 top
R16 "220R" 0402COM 18.13,33.247 r270 bottom
R17 "10k" 0402COM 20.086,31.062 r180 top
R18 "4.7R" 0402COM 21.077,31.062 r0 top
R20 "0R" 0402COM 7.44,22.626 r90 bottom
R21 "270R" 0402COM 5.329,35.152 r0 top
R22 "270R" 0402COM 7.618,31.745 r180 top
R23 "100k" 0402COM 20.647,10.944 r0 top
R24 "0R" 0402COM 11.369,32.038 r270 top
R25 "0R" 0402COM 10.353,32.038 r270 top
R26 "270R" 0402COM 3.909,32.659 r90 bottom
R27 "270R" 0402COM 1.225,30.2 r90 top
R28 "1k" 0402COM 15.638,10.737 r270 bottom
R29 "470R" 0402COM 9.337,30.946 r90 top
R30 "DNF" 0402COM 54.491,14.244 r180 top
R31 "DNF" 0402COM 46.632,13.178 r0 top
R32 "3.3R" 0402COM 33.381,9.314 r180 bottom
R33 "3.3R" 0402COM 46.504,10.016 r0 bottom
R34 "3.3R" 0402COM 46.504,11.312 r0 bottom
R35 "0R" 0402COM 46.632,11.146 r0 top
R36 "0R" 0402COM 46.632,12.162 r0 top
R37 "3.3R" 0402COM 46.505,13.285 r90 bottom
R38 "3.3R" 0402COM 33.391,12.314 r180 bottom
R39 "3.3R" 0402COM 33.391,13.289 r180 bottom
R40 "47k" 0402COM 30.224,10.073 r0 top
R41 "100k" 0402COM 30.224,9.048 r0 top
R42 "100k" 0402COM 30.224,8.048 r0 top
R43 "47k" 0402COM 32.274,6.973 r90 top
R44 "4.7k" 0402COM 31.773,4.973 r90 top
R45 "4.7k" 0402COM 32.757,5.998 r0 top
R46 "100k" 0402COM 33.381,10.304 r180 bottom
R47 "470k" 0402COM 32.291,14.289 r0 bottom
R48 "1k" 0402COM 35.882,5.023 r180 top
R49 "1k" 0402COM 35.769,3.014 r0 top
R50 "4.7k" 0402COM 32.62,15.223 r90 top
R51 "100k" 0402COM 37.932,4.023 r180 top
R52 "100R" 0402COM 39.257,3.84 r90 bottom
R53 "1.8k" 0402COM 34.677,17.535 r90 top
R54 "150R" 0402COM 37.907,1.948 r90 top
R55 "24R" 0402COM 36.907,0.948 r180 top
R56 "100R" 0402COM 39.249,1.761 r90 bottom
R57 "47k" 0402COM 33.712,17.535 r180 top
R58 "24R" 0402COM 46.2,2.002 r180 top
R59 "100R" 0402COM 40.741,3.84 r90 bottom
R60 "150R" 0402COM 42.091,1.973 r90 top
R61 "100R" 0402COM 40.748,1.761 r90 bottom
R62 "100k" 0402COM 43.141,4.023 r180 top
R63 "3.3R" 0402COM 36.765,17.532 r90 bottom
R64 "3.3R" 0402COM 42.855,17.543 r90 bottom
R65 "1k" 0402COM 44.116,3.023 r180 top
R66 "1k" 0402COM 44.066,5.023 r0 top
R67 "4.7k" 0402COM 46.149,3.957 r90 top
R68 "4.7k" 0402COM 47.191,2.941 r90 top
R69 "330k" 0402COM 42.297,18.652 r270 top
R70 "330k" 0402COM 37.705,18.65 r270 top
R71 "47k" 0402COM 47.191,6.091 r270 top
R72 "100k" 0402COM 47.724,7.082 r180 top
R73 "100k" 0402COM 47.724,8.098 r180 top
R74 "47k" 0402COM 47.724,9.114 r180 top
R75 "3.3R" 0402COM 43.805,17.543 r90 bottom
R76 "DNF" 0402COM 44.43,18.643 r270 top
R77 "3.3R" 0402COM 46.505,9.012 r0 bottom
R78 "3.3R" 0402COM 39.241,0.782 r270 bottom
R79 "270R" 0402COM 24.12,8.174 r0 top
R80 "0R" 0402COM 2.825,35.475 r0 top
R81 "100k" 0402COM 75.918,29.408 r90 bottom
R82 "0R" 0402COM 25.5,1.175 r90 top
R83 "100k" 0402COM 75.375,25.475 r0 bottom
R84 "100k" 0402COM 21.513,-5.108 r180 top
R85 "1k" 0402COM 75.025,38.15 r90 top
R86 "10R" 0402COM 70.639,39.197 r180 bottom
R87 "1k" 0402COM 63.412,33.788 r270 top
R88 "10R" 0402COM 69.492,31.694 r0 bottom
R89 "10R" 0402COM 65.414,39.222 r0 bottom
R90 "4.7R" 0402COM 63.457,39.297 r270 bottom
R91 "4.7R" 0402COM 62.335,34.205 r0 bottom
R92 "4.7R" 0402COM 74.225,34.675 r180 bottom
R93 "4.7R" 0402COM 71.625,40.25 r270 bottom
R94 "18R" 0402COM 72.588,29.637 r0 top
R95 "18R" 0402COM 71.632,29.658 r180 top
R96 "18R" 0402COM 70.538,30.688 r0 top
R97 "DNF" 0402COM 72.588,30.662 r0 top
R98 "10k" 0402COM 74.225,33.675 r180 bottom
R99 "10k" 0402COM 70.54,31.69 r0 top
R100 "DNF" 0402COM 71.4,33.725 r180 bottom
R101 "DNF" 0402COM 77.575,18.975 r90 top
R102 "DNF" 0402COM 79.775,16.975 r270 top
R103 "6.8k" 0402COM 78.775,15.875 r90 top
R104 "6.8k" 0402COM 78.775,12.825 r90 top
R105 "10k" 0402COM 63.548,25.192 r90 bottom
R106 "3.3R" 0402COM 66.8,18.308 r270 bottom
R107 "0R" 0402COM 59.51,19.629 r180 bottom
R108 "0R" 0402COM 59.51,18.588 r180 bottom
R109 "0R" 0402COM 59.5,25.925 r180 bottom
R110 "0R" 0402COM 59.5,24.875 r180 bottom
R111 "10R" 0402COM 64.006,28.265 r90 bottom
R112 "3.3R" 0402COM 68.044,18.308 r270 bottom
R113 "3.3R" 0402COM 64.793,18.308 r270 bottom
R114 "820R" 0402COM 74.525,14.025 r90 top
R115 "100k" 0402COM 66.063,28.265 r90 bottom
R116 "10R" 0402COM 65.047,29.357 r270 bottom
R117 "10R" 0402COM 71.625,24.575 r0 bottom
R118 "3.3R" 0402COM 71.626,23.439 r0 bottom
R119 "0R" 0402COM 71.575,23.225 r0 top
R120 "DNF" 0402COM 72.675,22.225 r180 top
R121 "DNF" 0402COM 73.7,22.125 r90 top
R122 "DNF" 0402COM 32.688,33.132 r180 top
R123 "100k" 0402COM 66.575,-0.9 r270 top
R124 "10k" 0402COM 66.475,-5.15 r180 top
R125 "10k" 0402COM 68.55,-0.9 r0 top
R126 "10k" 0402COM 61.975,-4.1 r90 top
R127 "47R" 0402COM 68.55,0.1 r0 top
R128 "47R" 0402COM 69.65,1.1 r0 top
R129 "1.8k" 0402COM 58.65,-7.25 r0 top
R130 "12R" 0402COM 58.35,-4 r90 bottom
R131 "12R" 0402COM 56.814,-4.003 r90 bottom
R132 "47R" 0402COM 68.225,7.725 r270 top
R133 "10R" 0402COM 29.184,30.455 r0 top
R134 "47R" 0402COM 72.325,7.75 r270 top
R135 "39R" 0402COM 44.274,-3.277 r0 top
R136 "150R" 0402COM 43.262,-2.167 r270 top
R137 "150R" 0402COM 46.38,-4.364 r90 top
R138 "180R" 0402COM 53.639,1.797 r270 bottom
R139 "DNF" 0402COM 27.872,16.691 r180 top
R140 "10R" 0402COM 7.437,11.42 r90 bottom
R141 "10R" 0402COM 0.6,11.425 r90 top
R142 "1M0" 0402COM 16.983,3.057 r90 top
R143 "DNF" 0402COM 31.225,22.2 r90 top
R144 "0R" 0402COM 20.086,32.104 r180 top
R145 "0R" 0402COM 28.425,21.225 r0 top
R146 "10R" 0402COM 7.437,16.856 r90 bottom
R147 "10R" 0402COM 0.625,17.775 r90 top
SW1 "MCIPTG23K-V" MCIPTG_SW 30.289,36.897 r0 top
T1 "MABA-007748" TX__AT224-1_ETC1-1T-75 51.796,10.152 r90 top
T2 "TC1-1-13M+" AT224-1 41.23,20.636 r180 top
T3 "TC4-14+" AT224-1 38.69,-0.135 r0 top
TL1 "1.5mm testloop (Y)" TESTLOOP_1.0MM 28.225,-0.25 r90 top
TL2 "1.5mm testloop (Y)" TESTLOOP_1.0MM 52.8,20.9 r90 top
TL3 "1.5mm testloop (Y)" TESTLOOP_1.0MM 52.093,25.954 r90 top
TL4 "1.5mm testloop (Y)" TESTLOOP_1.0MM 73.025,-5.3 r90 top
TL5 "1.5mm testloop (Y)" TESTLOOP_1.0MM 44.625,-5.8 r90 top
TL6 "1.5mm testloop (Y)" TESTLOOP_1.0MM 27.875,29.025 r90 top
TL7 "1.5mm testloop (Y)" TESTLOOP_1.0MM 49.85,21.425 r90 top
TL8 "1.5mm testloop (Y)" TESTLOOP_1.0MM 48.85,29.525 r90 top
TL9 "1.5mm testloop (Y)" TESTLOOP_1.0MM 28.325,9.025 r90 top
TL10 "1.5mm testloop (Y)" TESTLOOP_1.0MM 25.125,39.425 r90 top
TP1 "AUXDAC2" "1MM TSTPOINTV" 53.5,33.275 r90 top
TP2 "IRQN" "1.5MM TSTPOINTV" 24.305,32.786 r90 top
TP3 "PWR_DET" "1MM TSTPOINTV" 44.994,23.708 r90 top
TP4 "BVREF" "1.5MM TSTPOINTV" 32.154,19.299 r90 top
TP5 "998_FBQ" "1MM TSTPOINTV" 45.669,22.208 r270 top
TP6 "998_FBI" "1MM TSTPOINTV" 46.624,23.689 r0 top
TP8 "+3V3D" "1.5MM TSTPOINTV" 22.85,6.74 r90 top
TP9 "+3V3A" "1.5MM TSTPOINTV" 35.227,27.275 r180 top
TP10 "+3V3_VCO" "1.5MM TSTPOINTV" 76.675,37.175 r90 top
TP11 "GNDD" "1.5MM TSTPOINTV" 25.5,4 r270 top
TP12 "{SignalName}" "1.5MM TSTPOINTV" 79.125,21.525 r90 top
TP13 "+3V3A_TX" "1.5MM TSTPOINTV" 29.208,-3.205 r90 top
TP14 "{SignalName}" "1MM TSTPOINTV" 72.658,37.167 r90 top
TP15 "RXIP" "1MM TSTPOINTV" 59.444,21.358 r90 top
TP16 "RXIN" "1MM TSTPOINTV" 59.528,17.15 r180 top
TP17 "{SignalName}" "1.5MM TSTPOINTV" 68.85,27.825 r90 top
TP18 "RXQP" "1MM TSTPOINTV" 59.51,27.148 r0 top
TP19 "RXQN" "1MM TSTPOINTV" 59.44,23.303 r0 top
TP20 "VDDIO" "1.5MM TSTPOINTV" 62.405,28.494 r90 top
TP23 "VAPC" "1MM TSTPOINTV" 57.6,-5.25 r270 top
TP24 "SYSCLK1" "1MM TESTPOINT" 44.999,39.429 r90 top
TP25 "{SignalName}" "1MM TESTPOINT" 43.297,39.429 r90 top
TP26 "VBAT" "1MM TSTPOINTV" 23.125,34.525 r90 top
TR1 "MUN5214DW" SOT-363 22.273,15.593 r180 top
TR2 "MUN5214DW" SOT-363 21.759,10.052 r180 bottom
TR3 "MUN5214DW" SOT-363 7.211,33.98 r180 bottom
TR4 "MUN5214DW" SOT-363 18.457,16.833 r270 top
TR5 "MUN5214DW" SOT-363 4.976,30.196 r180 top
TR6 "BFR193W" SOT-323 76.375,14.15 r0 top
TR7 "BC856" SOT23_M 65.375,-4 r90 top
TR8 "BC856" SOT23_M 70.825,-0.9 r270 top
TR9 "BCW60D" SOT23_M 56.125,-7.25 r90 top
U1 "CMX998_Q1" "Q1_L1-L2 edge vias" 40,11.05 r90 top
U2 "RF5110G" "QFN-16 3X3 NF" 57.389,-0.303 r0 bottom locked
U3 "CMX994E_Q4" Q4-40B 66.8,23.338 r90 top
U4 "DS1818R-10+" SOT23_M 30.864,37.297 r180 bottom
U5 "LMX2571" "QFN127P600-9N-23-L1-L2 edge" 68.372,36.185 r0 top
U6 "CMX7364Q1" "Q1_L1-L2 edge vias" 41.517,32.778 r0 top
U7 "74AUP1G80" SOT-353 50.839,37.852 r270 bottom
U8 "74AHC1G04" SOT553 60.196,38.247 r0 bottom
U9 "MP08120" GTXO-91 56.376,33.28 r90 bottom
U10 "STM32F411VET6" LQFP100_N 17.629,21.008 r270 bottom locked
U11 "USBLC6-2" SOT23-6 10.354,34.64 r270 top
U12 "LP5907MFX-3.3" SOT23-5 18.557,5.114 r0 top
U13 "LP5907MFX-3.3" SOT23-5 32.631,24.098 r0 top
U14 "LP5907MFX-3.3" SOT23-5 79.042,29.967 r90 bottom
U15 "LP5907MFX-3.3" SOT23-5 77.433,25.762 r270 top
U16 "LP5907MFX-3.3" SOT23-5 23.561,-3.21 r0 top
U17 "NC7SZU04P5X" SC70-5 32.553,31.14 r180 top
U19 "STLQ015M18" SOT23-5L 21.986,36.788 r0 bottom
X1 "CM8V-T1A" XTAL_CM8V-T1A 15.417,32.593 r180 bottom

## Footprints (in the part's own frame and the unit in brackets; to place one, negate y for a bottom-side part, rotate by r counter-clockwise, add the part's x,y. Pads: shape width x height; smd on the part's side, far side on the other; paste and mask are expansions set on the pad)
"1.5MM Fiducial" [mm] "1.5mm disc in copper, 3mm disk in mask"
  round 1.5 smd far side paste-25.4 mask+0.2: 1(0,0)
  round 1.5 smd paste-25.4 mask+0.2: 1(0,0)
"1.5MM TSTPOINTV" [mm] "1.5mm testpoint with 0.3mm via"
  round 1.5 / inner round 0.7 / far side round 0.7 hole 0.3 paste-25.4: 1(0,0)
"1MM TESTPOINT" [mm]
  round 1 smd paste-25.4: 1(0,0)
"1MM TSTPOINTV" [mm] "1mm diam test point with 0.3mm via"
  round 1 / inner round 0.7 / far side round 0.7 hole 0.3 paste-25.4: 1(0,0)
2.2mmHole [mm] "2.2mm Mounting hole"
  round 4.5 hole 2.2 paste-5 mask-5: 0(0,0)
6LAYERBOX-SML [mm]
  Top lines w0.2: 2.3,0.75 1.15,0.75 ; 2.3,0.75 2.3,-0.75 ; 2.3,0.75 3.45,0.75 3.45,-0.75 2.3,-0.75 ; 2.3,-0.75 1.15,-0.75 ; 1.15,0.75 0,0.75 ; 1.15,0.75 1.15,-0.75 ; 1.15,-0.75 0,-0.75 ; 0,0.75 -1.15,0.75 ; 0,0.75 0,-0.75 ; 0,-0.75 -1.15,-0.75 ; -1.15,0.75 -2.3,0.75 ; -1.15,0.75 -1.15,-0.75 ; -1.15,-0.75 -2.3,-0.75 ; -2.3,0.75 -3.45,0.75 -3.45,-0.75 -2.3,-0.75 ; -2.3,0.75 -2.3,-0.75
  Bottom lines w0.2: 2.3,0.75 3.45,0.75 3.45,-0.75 2.3,-0.75 ; 2.3,0.75 2.3,-0.75 ; 2.3,0.75 1.15,0.75 ; 2.3,-0.75 1.15,-0.75 ; 1.15,0.75 1.15,-0.75 ; 1.15,0.75 0,0.75 ; 1.15,-0.75 0,-0.75 ; 0,0.75 0,-0.75 ; 0,0.75 -1.15,0.75 ; 0,-0.75 -1.15,-0.75 ; -1.15,0.75 -1.15,-0.75 ; -1.15,0.75 -2.3,0.75 ; -1.15,-0.75 -2.3,-0.75 ; -2.3,0.75 -2.3,-0.75 ; -2.3,0.75 -3.45,0.75 -3.45,-0.75 -2.3,-0.75
  Multi-Layer pour cut-out: -3.675,0.975 -3.675,-0.975 3.7,-0.975 3.7,0.975
0402COM [mm]
  rrect50% 0.55x0.6 smd: 1(0,0) 2(1.1,0)
  Top pour cut-out: 0.175,-0.3 0.175,0.3 0.95,0.3 0.95,-0.3
  silkscreen extent 0.45,-0.4 0.65,0.4, body extent 0.05,-0.28 1.05,0.27, height 0.38
0603COM [mm]
  rrect50% 0.75x1 smd: 1(0,0) 2(1.75,0)
  Top pour cut-out: 0.475,-0.65 0.475,0.65 1.275,0.65 1.275,-0.65
  silkscreen extent 0.63,-0.43 1.12,0.43, body extent -0.05,-0.48 1.8,0.48, height 0.45
0805COM [mm]
  rrect50% 1.2x1.4 smd: 1(0,0) 2(1.75,0)
  Top pour cut-out: 0.2,-0.8 0.2,0.8 1.55,0.8 1.55,-0.8
  silkscreen extent 0.7,-0.85 1.05,0.85, body extent -0.18,-0.7 1.92,0.7, height 0.5
1206COM [mm] "Chip CLR Body 3.2x1.6mm"
  rrect50% 1.25x1.8 smd: 1(0,0) 2(3.05,0)
  Top pour cut-out: 0.575,-0.9 2.475,-0.9 2.325,-0.75 2.325,0.75 2.475,0.9 0.575,0.9 0.725,0.75 0.725,-0.75
  silkscreen extent 0.8,-0.92 2.25,0.92, body extent -0.18,-0.86 3.22,0.86, height 1
1515SQ-82N [mm] "1515SQ-82N footprint, 7 x 4.5mm"
  rrect25% 1.775x4.45 smd: 1(-2.625,0) 2(2.625,0)
  Top pour cut-out: -2,-2 -2,2 2,2 2,-2
  silkscreen extent -1.43,-1.97 1.43,1.95, body extent -2.8,-1.87 2.8,1.88, height 3.9
AT224-1 [mm]
  rrect50% 0.8x1.75 smd: 1(0,0) 2(1.275,0) 3(2.55,0) 4(2.55,-3.2) 6(0,-3.2)
  silkscreen extent -0.7,-4.38 3.25,1.17
CML_LOGO [mm]
  silkscreen extent -6.01,-3.52 6.06,3.47
"DO-214AC SMA" [mm]
  rrect50% 2.2x1.7 smd: 1(0,0) 2(4.05,0)
  Top pour cut-out: 0.875,-1.125 3.25,-1.125 3.25,1.125 0.875,1.125
  silkscreen extent -1.6,-1.48 5.43,1.48
GTXO-91 [mm] "QFN, 4-Leads, Body 3.3x2.7mm (max), Pitch 1.75mm, Pitch1 2.20mm, IPC Medium Density"
  rect 1.3x1 smd: 1(0,0)
  rrect50% 1.3x1 smd: 2(2.95,0) 3(2.95,1.75) 4(0,1.75)
  Top pour cut-out: -0.5,0.5 0.65,0.5 0.65,-0.25 2.3,-0.25 2.3,0.475 3.5,0.475 3.5,1.275 2.3,1.275 2.3,2 0.65,2 0.65,1.275 -0.5,1.275
  silkscreen extent -0.97,-0.82 3.85,2.57, body extent -0.2,-0.45 3.15,2.2, height 1
Hdr_SMT_5x2_1p27Unsh [mm] "2x5 SMT header, 1.27mm pitch"
  rect 0.75x3 smd: 1(-2.55,-1.95)
  rrect50% 0.75x3 smd: 2(-2.55,1.95) 3(-1.275,-1.95) 4(-1.275,1.95) 5(0,-1.95) 6(0,1.95) 7(1.25,-1.95) 8(1.25,1.95) 9(2.525,-1.95) 10(2.525,1.95)
  silkscreen extent -3.35,-1.88 3.33,1.88
HSMF-C16x [mm] "Dual LED in 0603 size package"
  rrect50% 0.7x0.4 smd mask+0.075: 1(0,0) 2(0,-0.7) 3(1.3,0) 4(1.3,-0.7)
  Top pour cut-out: 0.575,0.6 0.575,-1.3 0.725,-1.3 0.725,0.6
  silkscreen extent 0.53,-1.1 2.45,0.4, body extent -0.15,-0.75 1.45,0.05, height 0.5
LED0603 [mm]
  rrect50% 0.8x0.8 smd: 1(0,0) 2(1.5,0)
  Top pour cut-out: 0.3,-0.5 1.225,-0.5 1.225,0.5 0.3,0.5
  silkscreen extent -0.6,-0.58 2.65,0.58
LQFP100_N [mm] "Thin QFP, 100-Leads, Body 14x14mm, Pitch 0.5mm, IPC Medium Density"
  oval 1.8x0.3 smd: 1(-7.55,6) 2(-7.55,5.5) 3(-7.55,5) 4(-7.55,4.5) 5(-7.55,4) 6(-7.55,3.5) 7(-7.55,3) 8(-7.55,2.5) 9(-7.55,2) 10(-7.55,1.5) 11(-7.55,1) 12(-7.55,0.5) 13(-7.55,0) 14(-7.55,-0.5) 15(-7.55,-1) 16(-7.55,-1.5) 17(-7.55,-2) 18(-7.55,-2.5) 19(-7.55,-3) 20(-7.55,-3.5) 21(-7.55,-4) 22(-7.55,-4.5) 23(-7.55,-5) 24(-7.55,-5.5) 25(-7.55,-6) 51(7.55,-6) 52(7.55,-5.5) 53(7.55,-5) 54(7.55,-4.5) 55(7.55,-4) 56(7.55,-3.5) 57(7.55,-3) 58(7.55,-2.5) 59(7.55,-2) 60(7.55,-1.5) 61(7.55,-1) 62(7.55,-0.5) 63(7.55,0) 64(7.55,0.5) 65(7.55,1) 66(7.55,1.5) 67(7.55,2) 68(7.55,2.5) 69(7.55,3) 70(7.55,3.5) 71(7.55,4) 72(7.55,4.5) 73(7.55,5) 74(7.55,5.5) 75(7.55,6)
  oval 0.3x1.8 smd: 26(-6,-7.55) 27(-5.5,-7.55) 28(-5,-7.55) 29(-4.5,-7.55) 30(-4,-7.55) 31(-3.5,-7.55) 32(-3,-7.55) 33(-2.5,-7.55) 34(-2,-7.55) 35(-1.5,-7.55) 36(-1,-7.55) 37(-0.5,-7.55) 38(0,-7.55) 39(0.5,-7.55) 40(1,-7.55) 41(1.5,-7.55) 42(2,-7.55) 43(2.5,-7.55) 44(3,-7.55) 45(3.5,-7.55) 46(4,-7.55) 47(4.5,-7.55) 48(5,-7.55) 49(5.5,-7.55) 50(6,-7.55) 76(6,7.55) 77(5.5,7.55) 78(5,7.55) 79(4.5,7.55) 80(4,7.55) 81(3.5,7.55) 82(3,7.55) 83(2.5,7.55) 84(2,7.55) 85(1.5,7.55) 86(1,7.55) 87(0.5,7.55) 88(0,7.55) 89(-0.5,7.55) 90(-1,7.55) 91(-1.5,7.55) 92(-2,7.55) 93(-2.5,7.55) 94(-3,7.55) 95(-3.5,7.55) 96(-4,7.55) 97(-4.5,7.55) 98(-5,7.55) 99(-5.5,7.55) 100(-6,7.55)
  silkscreen extent -7.67,-6.25 6.25,6.82, body extent -7,-7 7,7, height 1.6
M50-3602042 [mm] "20+20 pin SMT header"
  rrect50% 0.75x2.4 smd: 1(0,0) 2(0,3.9) 3(1.275,0) 4(1.275,3.9) 5(2.55,0) 6(2.55,3.9) 7(3.8,0) 8(3.8,3.9) 9(5.075,0) 10(5.075,3.9) 11(6.35,0) 12(6.35,3.9) 13(7.625,0) 14(7.625,3.9) 15(8.9,0) 16(8.9,3.9) 17(10.15,0) 18(10.15,3.9) 19(11.425,0) 20(11.425,3.9) 21(12.7,0) 22(12.7,3.9) 23(13.975,0) 24(13.975,3.9) 25(15.25,0) 26(15.25,3.9) 27(16.5,0) 28(16.5,3.9) 29(17.775,0) 30(17.775,3.9) 31(19.05,0) 32(19.05,3.9) 33(20.325,0) 34(20.325,3.9) 35(21.6,0) 36(21.6,3.9) 37(22.85,0) 38(22.85,3.9) 39(24.125,0) 40(24.125,3.9)
  silkscreen extent -1.4,-0.45 24.77,5.45, body extent -0.63,0.25 24.77,3.65, height 4.68
MCIPTG_SW [mm]
  rrect50% 0.9x1 smd: 1(-2.05,0.8) 2(-2.05,-0.8) 3(2.05,0.8) 4(2.05,-0.8)
  rrect50% 1.7x0.8 smd: 5(0,1.2)
  Top pour cut-out: -1.825,-1.4 -1.825,1.3 1.85,1.3 1.85,-1.4
  silkscreen extent -2.4,-1.5 2.4,1.6, body extent -2.17,-1.4 2.18,1.4, height 1.9
MKDS_2 [mm] "2-way screw terminal block, 3.5mm pitch"
  rrect25% 1.8x1.8 hole 1.1 mask+0: 1(0,0)
  round 1.8 hole 1.1 mask+0: 2(3.5,0)
  silkscreen extent -2.1,-4 5.6,3.8, body extent -2,-3.6 5.5,3.7, height 8.5
MOD1-8_BOX [mm]
  silkscreen extent -6.85,-0.63 11.4,1.28
"Q1_L1-L2 edge vias" [mm] "Q1 footprint GND vias L1-L2 only around edge of CMP"
  rrect50% 0.7x0.3 smd mask+0.175: 1(-4.55,3.75) 2(-4.55,3.25) 3(-4.55,2.75) 4(-4.55,2.25) 5(-4.55,1.75) 6(-4.55,1.25) 7(-4.55,0.75) 8(-4.55,0.25) 9(-4.55,-0.25) 10(-4.55,-0.75) 11(-4.55,-1.25) 12(-4.55,-1.75) 13(-4.55,-2.25) 14(-4.55,-2.75) 15(-4.55,-3.25) 16(-4.55,-3.75) 33(4.55,-3.75) 34(4.55,-3.25) 35(4.55,-2.75) 36(4.55,-2.25) 37(4.55,-1.75) 38(4.55,-1.25) 39(4.55,-0.75) 40(4.55,-0.25) 41(4.55,0.25) 42(4.55,0.75) 43(4.55,1.25) 44(4.55,1.75) 45(4.55,2.25) 46(4.55,2.75) 47(4.55,3.25) 48(4.55,3.75)
  rrect50% 0.3x0.7 smd mask+0.175: 17(-3.75,-4.55) 18(-3.25,-4.55) 19(-2.75,-4.55) 20(-2.25,-4.55) 21(-1.75,-4.55) 22(-1.25,-4.55) 23(-0.75,-4.55) 24(-0.25,-4.55) 25(0.25,-4.55) 26(0.75,-4.55) 27(1.25,-4.55) 28(1.75,-4.55) 29(2.25,-4.55) 30(2.75,-4.55) 31(3.25,-4.55) 32(3.75,-4.55) 49(3.75,4.55) 50(3.25,4.55) 51(2.75,4.55) 52(2.25,4.55) 53(1.75,4.55) 54(1.25,4.55) 55(0.75,4.55) 56(0.25,4.55) 57(-0.25,4.55) 58(-0.75,4.55) 59(-1.25,4.55) 60(-1.75,4.55) 61(-2.25,4.55) 62(-2.75,4.55) 63(-3.25,4.55) 64(-3.75,4.55)
  rect 7.95x7.95 smd paste-25.4 mask+0.2: 65(0,0)
  L2C lines w0.2: -3,3 -1,3 -1,1 ; 3,3 1,3 1,1 ; -3,1 -1,1 ; 3,1 1,1 ; -3,-1 -1,-1 ; 3,-1 1,-1 ; -3,-3 -1,-3 -1,-1 ; 3,-3 1,-3 1,-1 ; -1,1 0,0 ; 1,1 0,0 ; 0,0 -1,-1 ; 0,0 1,-1
  silkscreen extent -5.13,-5.12 5.12,5.13
Q4-40B [mm] "Outer GND vias layer 1-2, rest are top-bottom"
  oval 0.8x0.3 smd mask+0.125: 1(-2.875,2.25) 10(-2.875,-2.25) 21(2.875,-2.25) 30(2.875,2.25)
  rrect50% 0.8x0.3 smd mask+0.125: 2(-2.875,1.75) 3(-2.875,1.25) 4(-2.875,0.75) 5(-2.875,0.25) 6(-2.875,-0.25) 7(-2.875,-0.75) 8(-2.875,-1.25) 9(-2.875,-1.75) 22(2.875,-1.75) 23(2.875,-1.25) 24(2.875,-0.75) 25(2.875,-0.25) 26(2.875,0.25) 27(2.875,0.75) 28(2.875,1.25) 29(2.875,1.75)
  oval 0.3x0.8 smd mask+0.125: 11(-2.25,-2.875) 20(2.25,-2.875) 31(2.25,2.875) 40(-2.25,2.875)
  rrect50% 0.3x0.8 smd mask+0.125: 12(-1.75,-2.875) 13(-1.25,-2.875) 14(-0.75,-2.875) 15(-0.25,-2.875) 16(0.25,-2.875) 17(0.75,-2.875) 18(1.25,-2.875) 19(1.75,-2.875) 32(1.75,2.875) 33(1.25,2.875) 34(0.75,2.875) 35(0.25,2.875) 36(-0.25,2.875) 37(-0.75,2.875) 38(-1.25,2.875) 39(-1.75,2.875)
  rect 4.3x4.3 smd paste-25.4 mask+0.05: 41(0,0)
  L2C lines w0.2: -1.8,1.8 -0.9,1.8 -0.9,0.9 ; 0,1.8 0,0.9 ; 0.9,1.8 0.9,0.9 ; 1.8,1.8 1.8,0.9 0.9,0.9 ; -1.8,0.9 -0.9,0.9 ; -1.8,0 -0.9,0 ; 1.8,0 0.9,0 ; 1.8,-0.9 0.9,-0.9 ; -1.8,-1.8 -1.8,-0.9 -0.9,-0.9 ; -0.9,-1.8 -0.9,-0.9 ; 0,-1.8 0,-0.9 ; 1.8,-1.8 0.9,-1.8 0.9,-0.9 ; -0.9,0.9 0,0.9 ; 0,0.9 0,0 ; 0.9,0.9 0.9,0 ; -0.9,0 0,0 ; -0.9,0 -0.9,-0.9 ; 0,0 0,-0.9 ; 0,0 0.9,0 ; 0,-0.9 0.9,-0.9
  silkscreen extent -3.58,-3.57 3.57,3.58, body extent -3,-4.03 3,3, height 3
"QFN127P600-9N-23-L1-L2 edge" [mm] "6mm sq QFN 36-pin, 0.5mm  with CMP, L1-L2 GND vias at edge"
  rrect50% 0.8x0.25 smd mask+0.05: 1(-3,2) 2(-3,1.5) 3(-3,1) 4(-3,0.5) 5(-3,0) 6(-3,-0.5) 7(-3,-1) 8(-3,-1.5) 9(-3,-2) 19(3,-2) 20(3,-1.5) 21(3,-1) 22(3,-0.5) 23(3,0) 24(3,0.5) 25(3,1) 26(3,1.5) 27(3,2)
  rrect50% 0.25x0.8 smd mask+0.05: 10(-2,-3) 11(-1.5,-3) 12(-1,-3) 13(-0.5,-3) 14(0,-3) 15(0.5,-3) 16(1,-3) 17(1.5,-3) 18(2,-3) 28(2,3) 29(1.5,3) 30(1,3) 31(0.5,3) 32(0,3) 33(-0.5,3) 34(-1,3) 35(-1.5,3) 36(-2,3)
  rect 4.6x4.6 smd paste-4 mask+0.05: 37(0,0)
  silkscreen extent -3.25,-3.2 3.2,3.25, body extent -3.05,-3.05 3.05,3.05, height 0.8
"QFN-16 3X3 NF" [mm] "RF5110G footprint with no 'Fill Vias' layer"
  rrect50% 1x0.3 smd mask+0.125: 1(0,0) 2(0,-0.5) 3(0,-1) 4(0,-1.5) 9(3,-1.5) 10(3,-1) 11(3,-0.5) 12(3,0)
  rrect50% 0.3x1 smd mask+0.125: 5(0.75,-2.25) 6(1.25,-2.25) 7(1.75,-2.25) 8(2.25,-2.25) 13(2.25,0.75) 14(1.75,0.75) 15(1.25,0.75) 16(0.75,0.75)
  rect 1.5x1.5 smd mask+0.25: 17(1.5,-0.75)
  L2C lines w0.2: 1,-0.25 1.5,-0.75 ; 1,-1.25 1.5,-0.75 ; 2,-0.25 1.5,-0.75 ; 2,-1.25 1.5,-0.75
  silkscreen extent -0.5,-2.75 3.5,1.25
"RG178 PAD" [mm]
  rrect50% 1.5x3 smd: 1(0,0)
  rrect50% 4x2 smd: 2(0,-3.5)
SC70-5 [mm] "SOT23127P600-8N"
  rrect50% 0.8x0.4 smd mask+0.15: 1(-0.95,0.65) 2(-0.95,0) 3(-0.95,-0.65) 4(0.95,-0.65) 5(0.95,0.65)
  silkscreen extent -0.45,-1.1 0.72,1.1, body extent -0.67,-1.1 0.67,1.1, height 1
Serial-small [mm] "10x5mm S/N box"
  silkscreen extent 0,-5 10,0
SMA_ENDLAUNCH_J502 [mm] "Pads for end-launch SMA with 0.762mm signal pin"
  rrect50% 1.2x5.1 smd paste-2: 1(0,0)
  rrect50% 1.6x5.4 / inner round 0.8 / far side rrect50% 1.6x5.4 hole 0.3 paste+0.2: 2(-4.325,0.1)
  rrect50% 1.6x5.4 / inner round 0.8 / far side rrect50% 1.6x5.4 hole 0.3: 3(4.325,0.1)
  silkscreen extent -5.58,-3 5.58,2.3
SOD323 [mm] "Diode, body 1.4x1.8mm (max), IPC Med Density"
  rrect50% 0.85x0.85 smd: 1(0,0)
  rrect50% 0.75x0.85 smd: 2(2.65,0)
  Top pour cut-out: 0.55,0.625 0.575,0.6 2.05,0.6 2.05,-0.625 0.55,-0.625
  silkscreen extent -0.63,-0.8 3.28,0.8, body extent 0.43,-0.67 2.23,0.67, height 1.1
SOD-523 [mm] "2-pin Diode, 1.6mm x 0.8mm"
  rrect50% 0.48x0.4 smd: 1(-0.65,0) 2(0.65,0)
  Top pour cut-out: -0.475,-0.425 0.5,-0.425 0.5,0.425 -0.475,0.425
  silkscreen extent -1.07,-0.62 1.07,0.63, body extent -0.65,-0.45 0.65,0.45, height 0.7
SOT23-5 [mm]
  rrect50% 1x0.65 smd mask+0.175: 1(0,0) 2(0,-0.95) 3(0,-1.9) 4(2.6,-1.9) 5(2.6,0)
  silkscreen extent -0.4,-2.52 3,0.63
SOT23-5L [mm] "SOT23127P600-8N"
  rrect50% 1.2x0.6 smd: 1(-1.15,0.95) 2(-1.15,0) 3(-1.15,-0.95) 4(1.15,-0.95) 5(1.15,0.95)
  silkscreen extent -0.48,-1.5 1.15,1.5, body extent -0.8,-1.47 0.8,1.48, height 1.45
SOT23-6 [mm]
  rect 1.2x0.6 smd mask+0.175: 1(-1.15,0.95)
  rrect50% 1.2x0.6 smd mask+0.175: 2(-1.15,0) 3(-1.15,-0.95) 4(1.15,-0.95) 5(1.15,0) 6(1.15,0.95)
  silkscreen extent -1.9,-1.55 0.25,1.9, body extent -0.87,-1.52 0.87,1.53, height 1.45
SOT23_M [mm]
  rrect50% 0.8x0.9 smd: 1(0,0) 2(2,0) 3(1,2.2)
  Top pour cut-out: -0.625,0.4 2.675,0.4 2.675,1.85 -0.625,1.85
  silkscreen extent -0.5,-0.05 2.55,1.73
SOT323 [mm]
  rrect50% 0.6x0.9 smd: 1(0,0) 2(1.3,0) 3(0.65,1.6)
  Top pour cut-out: 1.575,0.525 -0.25,0.525 -0.25,1.5 0.275,1.5 0.275,1.075 1.025,1.075 1.025,1.5 1.575,1.5
  silkscreen extent -0.35,0 1.65,1.6
SOT553 [mm]
  rrect50% 0.6x0.275 smd mask+0.15: 1(-0.75,0.5) 2(-0.75,0) 3(-0.75,-0.5)
  rrect50% 0.6x0.275 smd: 4(0.75,-0.5) 5(0.75,0.5)
  silkscreen extent -0.3,-0.82 0.55,0.82
SOT-323 [mm] "SOT323 footprint"
  rrect50% 0.6x0.8 smd: 1(-0.65,-0.8) 2(0.65,-0.8) 3(0,0.8)
  Top pour cut-out: 1.05,-0.5 -1.05,-0.5 -1.05,0.7 -0.375,0.7 -0.375,0.275 0.375,0.275 0.375,0.7 1.05,0.7
  silkscreen extent -1.1,0.07 1.1,0.67, body extent -1.1,-0.67 1.1,0.67, height 1
SOT-353 [mm] "SOT23127P600-8N   (=SC70-5)"
  rrect50% 0.8x0.4 smd mask+0.15: 1(-0.95,0.65) 2(-0.95,0) 3(-0.95,-0.65) 4(0.95,-0.65) 5(0.95,0.65)
  silkscreen extent -0.45,-1.1 0.72,1.1, body extent -0.67,-1.1 0.67,1.1, height 1
SOT-363 [mm]
  rect 0.889x0.406 smd mask+0.125: 1(0,0)
  rrect50% 0.889x0.406 smd mask+0.125: 2(0,-0.65) 3(0,-1.3) 4(1.9,-1.3) 5(1.9,-0.65) 6(1.9,0)
  silkscreen extent -0.72,-1.8 2.63,0.5
TAJ_A_M [mm]
  rrect50% 1.8x1.25 smd: 1(0,0) 2(2.6,0)
  Top pour cut-out: 0.8,-0.725 1.8,-0.725 1.6,-0.525 1.6,0.525 1.8,0.725 0.8,0.725 1,0.525 1,-0.525
  silkscreen extent -0.82,-1.1 3,1.07
TESTLOOP_1.0MM [mm]
  round 1.5 hole 1: 1(0,0)
TINYPAD [mm]
  rrect50% 0.2x0.2 smd paste-25.4 mask+0.05: 1(0,0)
TX__AT224-1_ETC1-1T-75 [mm]
  rrect50% 0.8x1.75 smd: 1(0,0) 2(1.275,0) 3(2.55,0) 4(2.55,-3.2) 6(0,-3.2)
  Top pour cut-out: -0.6,-2.55 0.35,-2.55 0.35,-4.25 2.2,-4.25 2.2,-2.55 3.15,-2.55 3.15,-0.65 2.15,-0.65 2.15,0.7 0.4,0.7 0.4,-0.65 -0.6,-0.65
  silkscreen extent -0.7,-4.38 3.25,1.17
USB-MICRO-B-ZX62 [mm] "R/A USB Micro-B receptacle ( Hirose ZX62 )"
  rrect50% 0.4x1.35 smd mask+0.125: 1(-1.3,2.675) 2(-0.65,2.675) 3(0,2.675) 4(0.65,2.675) 5(1.3,2.675)
  rrect50% 2.1x1.6 smd: 6(-3.075,2.55) 7(3.1,2.55)
  rrect50% 1.9x1.9 smd: 8(-4,0) 9(-1.2,0) 10(1.2,0) 11(4,0)
  Top pour cut-out: -3.85,-1.45 -3.85,1.75 -3.575,1.75 -3.325,2 2.95,2 3.2,1.75 3.85,1.75 3.85,-1.45
  body extent -4.1,-2.6 4.1,2.95, height 2.8
XTAL_CM8V-T1A [mm] "SMT Xtal 2mm x 1.2mm   CAPM3216X18N"
  rrect50% 1x1.4 smd: 1(-0.85,0) 2(0.85,0)
  body extent -1.03,-0.63 1.02,0.63, height 0.6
